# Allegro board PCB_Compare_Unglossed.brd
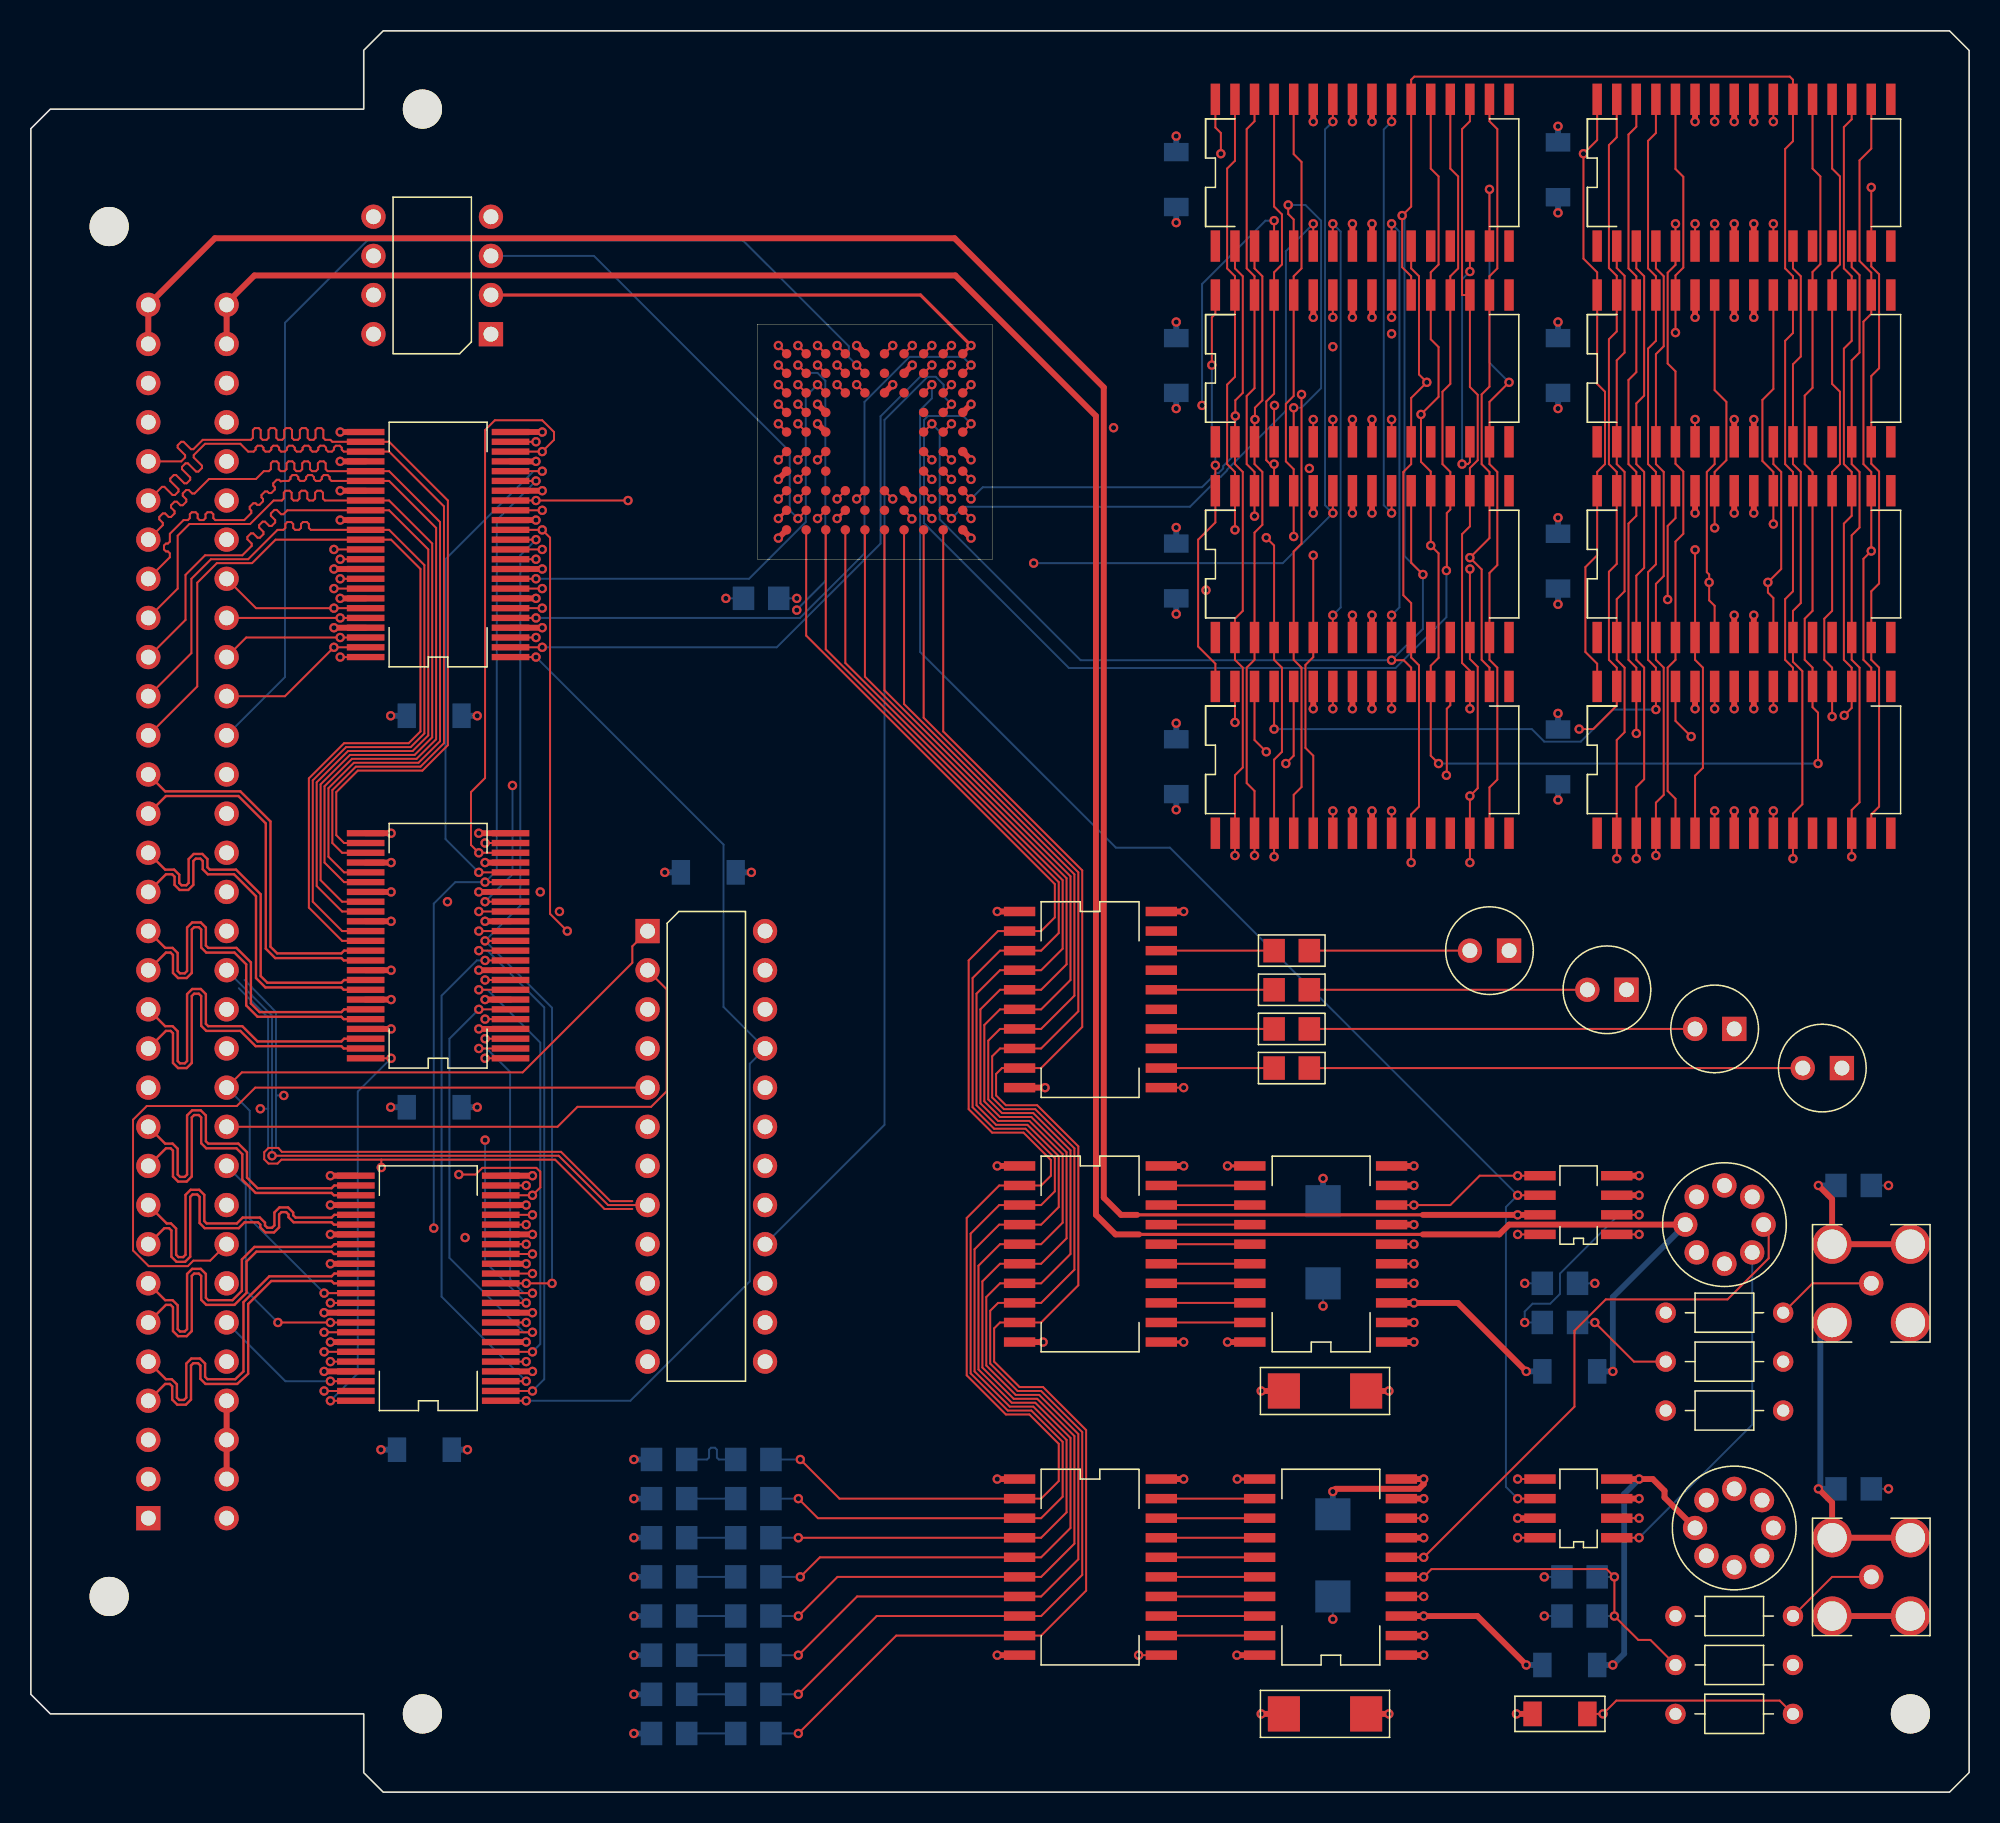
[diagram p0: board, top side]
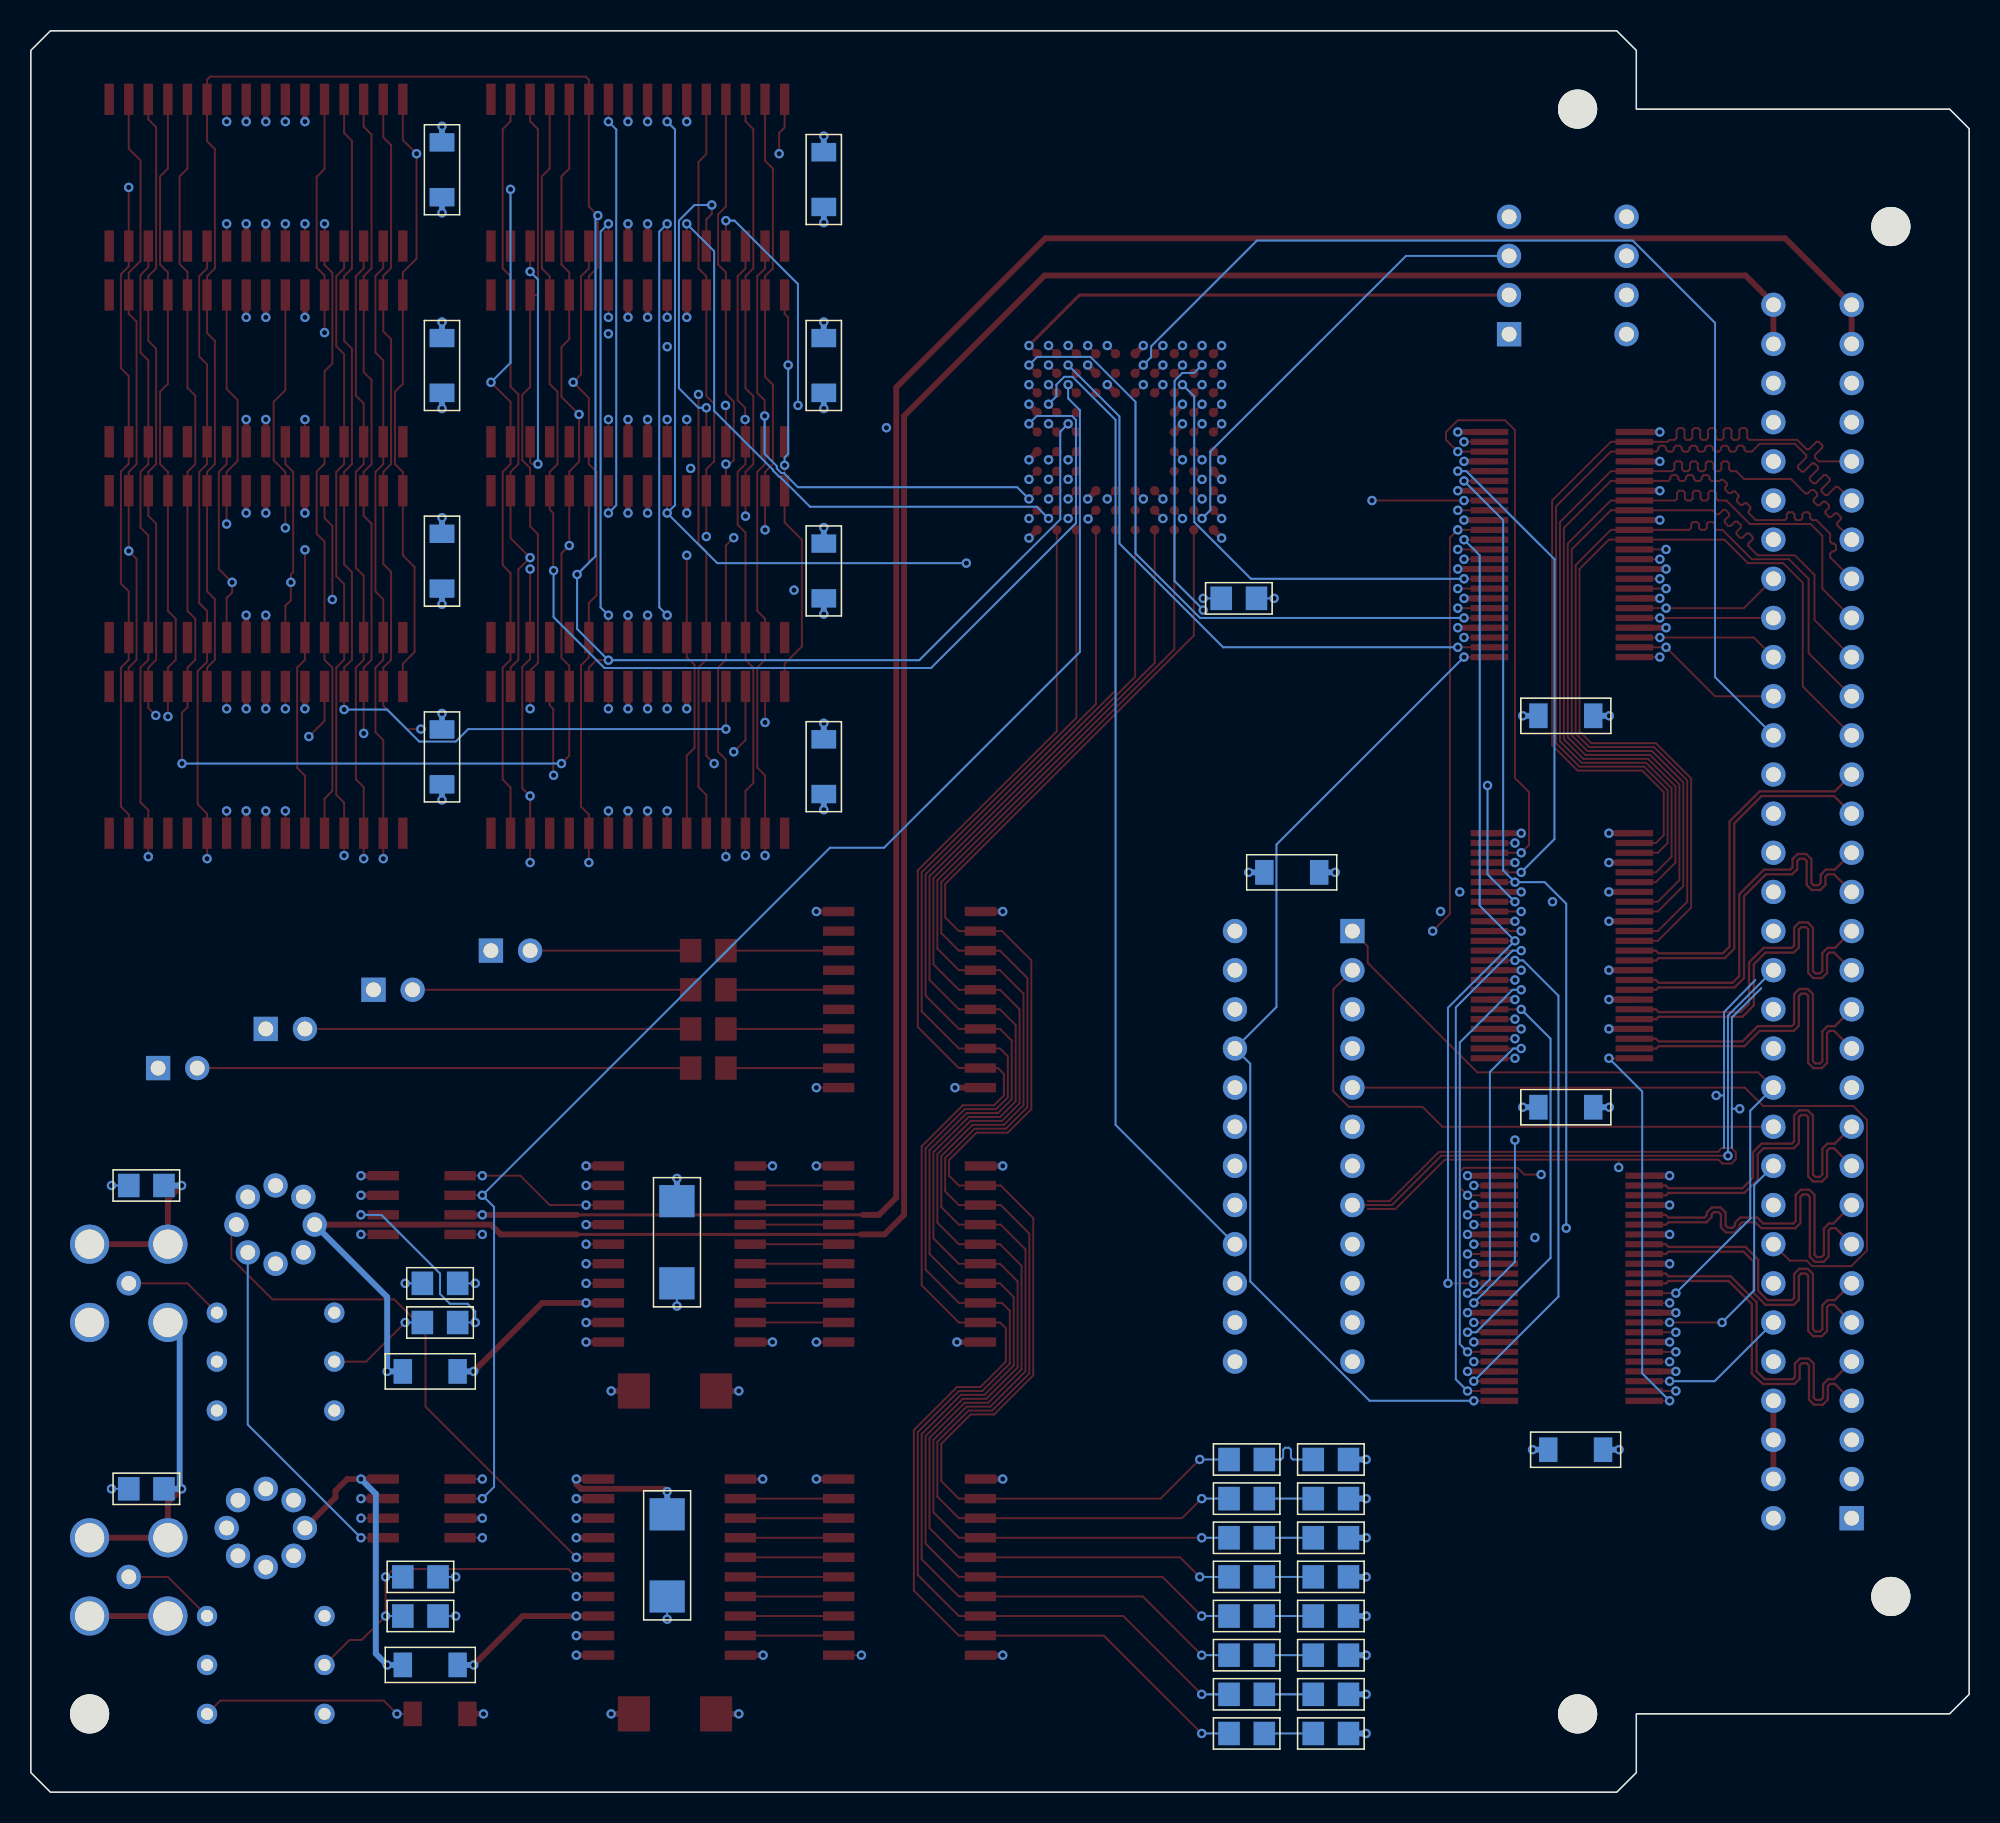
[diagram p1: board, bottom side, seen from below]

Outline 125.73 x 114.3 mm; copper layers: TOP, GND, INNER_1, INNER_2, VCC, BOTTOM. Coordinates in mm from the lower left corner of the outline.

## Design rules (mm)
constraint set DEFAULT: min track width 0.127
net group BNC2: nets BNC2 OUTA
net group BNC3: nets BNC3 OUTB
net group DC_NETS: nets AGND GND_EARTH
net group DP_A8_A9: nets A8 A9
net group DP_A10_A11: nets A10 A11
net group DP_A12_A13: nets A12 A13
net group DP_A14_A15: nets A14 A15
net group DP_D8_D9: nets D8 D9
net group DP_D10_D11: nets D10 D11
net group DP_D12_D13: nets D12 D13
net group DP_D14_D15: nets D14 D15
net group Q0: nets Q0 Q1
net group Q2: nets Q2 Q3
net group Q4: nets Q4 Q5
net group Q6: nets Q6 Q7
net group VCLKC: nets N409523 VCLKC
net group VD0: nets N14855 VD0
net group VD1: nets N14853 VD1
net group VD2: nets N14849 VD2
net group VD3: nets N14843 VD3
net group VD4: nets N15161 VD4
net group VD5: nets N15155 VD5
net group VD6: nets N15151 VD6
net group VD7: nets N15143 VD7
net group CLOCK: nets DCLK MCLK VCLKA
net group N00036: nets N00036 N282866 N282912
net group N00036_12287: nets N00036_12287 N282866_12286 N282912_12285
net group VREF: nets N00038 N00038_12290 VREF
nets with their own width: min track width 0.381; nets GND V12N V+12 VCC

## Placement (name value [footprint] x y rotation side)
C1  0.1uF  [SM_1206]  27.3 22.23 180 bottom
C2  0.1uF  [SM_1206]  27.94 44.45 180 bottom
C3  0.1uF  [SM_1206]  27.94 69.85 180 bottom
C4  0.1uF  [SM_1206]  45.72 59.69 180 bottom
C5  47PF  [SM_0805]  119.38 39.37 180 bottom
C6  47PF  [SM_0805]  119.38 19.69 180 bottom
C7  3300  [SM_0805]  42.55 6.35 180 bottom
C8  3300  [SM_0805]  42.55 11.43 180 bottom
C9  3300  [SM_0805]  42.55 16.51 180 bottom
C10  3300  [SM_0805]  42.55 21.59 180 bottom
C11  3300  [SM_0805]  42.55 3.81 180 bottom
C12  3300  [SM_0805]  42.55 8.89 180 bottom
C13  3300  [SM_0805]  42.55 13.97 180 bottom
C14  3300  [SM_0805]  42.55 19.05 180 bottom
C15  0.1uF  [SM_1206]  99.06 103.5 90 bottom
C16  0.1uF  [SM_1206]  99.06 78.11 90 bottom
C17  0.1uF  [SM_1206]  99.06 90.8 90 bottom
C18  0.1uF  [SM_1206]  74.3 102.87 90 bottom
C19  0.1uF  [SM_1206]  99.06 65.41 90 bottom
C20  0.1uF  [SM_1206]  74.3 90.8 90 bottom
C21  0.1uF  [SM_1206]  74.3 77.47 90 bottom
C22  0.1uF  [SM_1206]  74.3 64.77 90 bottom
C23  .01uF  [SMC_6032]  81.28 26.03 0 top
C24  .01uF  [SMC_6032]  83.82 33.02 90 bottom
C25  0.1uF  [SM_1206]  101.6 27.3 180 bottom
C26  .01uF  [SMC_6032]  81.28 5.08 0 top
C27  .01uF  [SMC_6032]  84.45 12.7 90 bottom
C28  0.1uF  [SM_1206]  101.6 8.25 180 bottom
D1  -  [LED]  95.88 54.61 180 top
D2  -  [LED]  103.5 52.07 180 top
D3  -  [LED]  110.49 49.53 180 top
D4  -  [LED]  117.47 46.99 180 top
J1  CON64  [DIN64]  7.62 17.78 0 top
J2  -  [BNC]  119.38 33.02 0 top
J3  -  [BNC]  119.38 13.97 0 top
L1  50  [IND300]  106.04 31.12 0 top
L2  50  [IND300]  106.68 11.43 0 top
L3  50  [IND300]  113.66 24.77 180 top
L4  50  [IND300]  113.66 27.94 180 top
L5  50  [IND300]  114.3 5.08 180 top
L6  50  [IND300]  114.3 8.25 180 top
NOREF  -  []  -30.48 -55.88 0 top
NOREF#2  -  []  259.08 129.54 0 top
NOREF#3  -  [unnamed#2]  25.4 5.08 0 top
R1  150  [SM_0805]  80.64 54.61 0 top
R2  150  [SM_0805]  80.64 52.07 0 top
R3  150  [SM_0805]  80.64 49.53 0 top
R4  150  [SM_0805]  80.64 46.99 0 top
R5  2K  [SM_0805]  48.51 77.47 180 bottom
R6  10K  [SM_0805]  45.72 6.35 0 bottom
R7  10K  [SM_0805]  45.72 11.43 0 bottom
R8  10K  [SM_0805]  45.72 16.51 0 bottom
R9  10K  [SM_0805]  45.72 21.59 0 bottom
R10  10K  [SM_0805]  45.72 3.81 0 bottom
R11  10K  [SM_0805]  45.72 8.89 0 bottom
R12  10K  [SM_0805]  45.72 13.97 0 bottom
R13  10K  [SM_0805]  45.72 19.05 0 bottom
R14  1/4w  [SM_1206]  100.97 5.08 180 top
R15  100  [SM_0805]  100.33 30.48 180 bottom
R16  100  [SM_0805]  100.33 33.02 180 bottom
R17  100  [SM_0805]  101.6 13.97 180 bottom
R18  100  [SM_0805]  101.6 11.43 180 bottom
U1  FCT16245  [SOIC48]  30.48 25.4 180 top
U2  20L10  [DIP24]  40 55.88 0 top
U3  FCT16245  [SOIC48]  31.11 47.62 180 top
U4  FCT16245  [SOIC48]  31.11 73.66 180 top
U5  EPF8282A_LCC  [BGA_84]  54.74 87.63 0 top
U6  74ACT574  [SOIC20]  64.13 57.15 0 top
U7  EPC1064  [DIP8]  29.84 94.61 180 top
U8  74ACT574  [SOIC20]  64.13 40.64 0 top
U9  74ACT574  [SOIC20]  64.13 20.32 0 top
U10  TC55B4257  [SOIC32]  76.84 62.23 90 top
U11  TC55B4257  [SOIC32]  101.6 100.33 90 top
U12  TC55B4257  [SOIC32]  101.6 62.23 90 top
U13  TC55B4257  [SOIC32]  76.84 87.63 90 top
U14  TC55B4257  [SOIC32]  76.84 74.93 90 top
U15  TC55B4257  [SOIC32]  76.84 100.33 90 top
U16  TC55B4257  [SOIC32]  101.6 74.93 90 top
U17  TC55B4257  [SOIC32]  101.6 87.63 90 top
U18  TLC5602A  [SOIC20]  88.27 29.21 180 top
U19  DG419AK  [SOIC8]  102.87 36.2 180 top
U20  TLE2037A  [TO-99]  110.49 17.14 0 top
U21  TLC5602A  [SOIC20]  88.9 8.89 180 top
U22  TLE2037A  [TO-99]  109.85 36.83 0 top
U23  DG419AK  [SOIC8]  102.87 16.51 180 top

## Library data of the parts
C1-C4 = CAP NP: signal model: DEFAULT_CAPACITOR_100000pF_2_1
C5 = CAP: signal model: DEFAULT_CAPACITOR_47pF_2_1; room: CHAN1
C6 = CAP: signal model: DEFAULT_CAPACITOR_47pF_2_1; room: CHAN2
C7-C14 = CAP: signal model: DEFAULT_RESISTOR_3300OHM_2_1
C15-C22 = CAP NP: signal model: DEFAULT_CAPACITOR_100000pF_2_1; room: MEM
C23 C24 = CAP: signal model: DEFAULT_CAPACITOR_10000pF_2_1; room: CHAN1
C25 = CAP NP: signal model: DEFAULT_CAPACITOR_100000pF_2_1; room: CHAN1
C26 C27 = CAP: signal model: DEFAULT_CAPACITOR_10000pF_2_1; room: CHAN2
C28 = CAP NP: signal model: DEFAULT_CAPACITOR_100000pF_2_1; room: CHAN2
D1-D4 = PHOTODIODE
J1 = CON64
J2 = BNC: alternate symbols: (bnc1); room: CHAN1
J3 = BNC: alternate symbols: (bnc1); room: CHAN2
L1 L3 L4 = INDUCTOR: signal model: DEFAULT_RESISTOR_50OHM_2_1; room: CHAN1
L2 L5 L6 = INDUCTOR: signal model: DEFAULT_RESISTOR_50OHM_2_1; room: CHAN2
R1-R4 = R: signal model: DEFAULT_RESISTOR_150OHM_2_1; room: LED
R5 = R: signal model: DEFAULT_RESISTOR_2000OHM_2_1
R6-R13 = R: signal model: DEFAULT_RESISTOR_10000OHM_2_1
R14 = R: signal model: DEFAULT_RESISTOR_0.25OHM_2_1; room: CHAN2
R15 R16 = R: signal model: DEFAULT_RESISTOR_100OHM_2_1; room: CHAN1
R17 R18 = R: signal model: DEFAULT_RESISTOR_100OHM_2_1; room: CHAN2
U1 U3 U4 = FCT16245
U2 = 20L10: alternate symbols: (T:SOIC24;B:SOIC24_PE)
U5 = EPF8282A/LCC_2
U6 = 74ACT574: room: LED
U7 = EPC1064
U8 = 74ACT574: room: CHAN1
U9 = 74ACT574: room: CHAN2
U10-U17 = TC55B4257: room: MEM
U18 = TLC5602A: room: CHAN1
U19 = DG419AK: room: CHAN1
U20 = TLE2037A: room: CHAN1
U21 = TLC5602A: room: CHAN2
U22 = TLE2037A: room: CHAN2
U23 = DG419AK: room: CHAN2

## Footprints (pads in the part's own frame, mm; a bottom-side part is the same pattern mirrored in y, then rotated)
BGA_84
  round 0.61 smd: A1(-5.715,5.715) A2(-4.445,5.715) A3(-3.175,5.715) A4(-1.905,5.715) A5(-0.635,5.715) A6(0.635,5.715) A7(1.905,5.715) A8(3.175,5.715) A9(4.445,5.715) A10(5.715,5.715) B1(-5.715,4.445) B2(-4.445,4.445) B3(-3.175,4.445) B4(-1.905,4.445) B5(-0.635,4.445) B6(0.635,4.445) B7(1.905,4.445) B8(3.175,4.445) B9(4.445,4.445) B10(5.715,4.445) C1(-5.715,3.175) C2(-4.445,3.175) C3(-3.175,3.175) C4(-1.905,3.175) C5(-0.635,3.175) C6(0.635,3.175) C7(1.905,3.175) C8(3.175,3.175) C9(4.445,3.175) C10(5.715,3.175) D1(-5.715,1.905) D2(-4.445,1.905) D3(-3.175,1.905) D8(3.175,1.905) D9(4.445,1.905) D10(5.715,1.905) E1(-5.715,0.635) E2(-4.445,0.635) E3(-3.175,0.635) E8(3.175,0.635) E9(4.445,0.635) E10(5.715,0.635) F1(-5.715,-0.635) F2(-4.445,-0.635) F3(-3.175,-0.635) F8(3.175,-0.635) F9(4.445,-0.635) F10(5.715,-0.635) G1(-5.715,-1.905) G2(-4.445,-1.905) G3(-3.175,-1.905) G8(3.175,-1.905) G9(4.445,-1.905) G10(5.715,-1.905) H1(-5.715,-3.175) H2(-4.445,-3.175) H3(-3.175,-3.175) H4(-1.905,-3.175) H5(-0.635,-3.175) H6(0.635,-3.175) H7(1.905,-3.175) H8(3.175,-3.175) H9(4.445,-3.175) H10(5.715,-3.175) J1(-5.715,-4.445) J2(-4.445,-4.445) J3(-3.175,-4.445) J4(-1.905,-4.445) J5(-0.635,-4.445) J6(0.635,-4.445) J7(1.905,-4.445) J8(3.175,-4.445) J9(4.445,-4.445) J10(5.715,-4.445) K1(-5.715,-5.715) K2(-4.445,-5.715) K3(-3.175,-5.715) K4(-1.905,-5.715) K5(-0.635,-5.715) K6(0.635,-5.715) K7(1.905,-5.715) K8(3.175,-5.715) K9(4.445,-5.715) K10(5.715,-5.715)
BNC
  round 1.575 hole 0.965: 1(0,0)
  round 2.54 hole 1.905: 2(-2.54,2.54) 3(-2.54,-2.54) 4(2.54,2.54) 5(2.54,-2.54)
DIN64
  round 2.54 hole 2.794 unplated: (-2.54,83.82) (-2.54,-5.08)
  rect 1.575x1.575 hole 0.965: 1(0,0)
  round 1.575 hole 0.965: 2(0,2.54) 3(0,5.08) 4(0,7.62) 5(0,10.16) 6(0,12.7) 7(0,15.24) 8(0,17.78) 9(0,20.32) 10(0,22.86) 11(0,25.4) 12(0,27.94) 13(0,30.48) 14(0,33.02) 15(0,35.56) 16(0,38.1) 17(0,40.64) 18(0,43.18) 19(0,45.72) 20(0,48.26) 21(0,50.8) 22(0,53.34) 23(0,55.88) 24(0,58.42) 25(0,60.96) 26(0,63.5) 27(0,66.04) 28(0,68.58) 29(0,71.12) 30(0,73.66) 31(0,76.2) 32(0,78.74) 33(5.08,0) 34(5.08,2.54) 35(5.08,5.08) 36(5.08,7.62) 37(5.08,10.16) 38(5.08,12.7) 39(5.08,15.24) 40(5.08,17.78) 41(5.08,20.32) 42(5.08,22.86) 43(5.08,25.4) 44(5.08,27.94) 45(5.08,30.48) 46(5.08,33.02) 47(5.08,35.56) 48(5.08,38.1) 49(5.08,40.64) 50(5.08,43.18) 51(5.08,45.72) 52(5.08,48.26) 53(5.08,50.8) 54(5.08,53.34) 55(5.08,55.88) 56(5.08,58.42) 57(5.08,60.96) 58(5.08,63.5) 59(5.08,66.04) 60(5.08,68.58) 61(5.08,71.12) 62(5.08,73.66) 63(5.08,76.2) 64(5.08,78.74)
DIP8
  rect 1.575x1.575 hole 0.965: 1(0,0)
  round 1.575 hole 0.965: 2(0,-2.54) 3(0,-5.08) 4(0,-7.62) 5(7.62,-7.62) 6(7.62,-5.08) 7(7.62,-2.54) 8(7.62,0)
DIP24
  rect 1.575x1.575 hole 0.965: 1(0,0)
  round 1.575 hole 0.965: 2(0,-2.54) 3(0,-5.08) 4(0,-7.62) 5(0,-10.16) 6(0,-12.7) 7(0,-15.24) 8(0,-17.78) 9(0,-20.32) 10(0,-22.86) 11(0,-25.4) 12(0,-27.94) 13(7.62,-27.94) 14(7.62,-25.4) 15(7.62,-22.86) 16(7.62,-20.32) 17(7.62,-17.78) 18(7.62,-15.24) 19(7.62,-12.7) 20(7.62,-10.16) 21(7.62,-7.62) 22(7.62,-5.08) 23(7.62,-2.54) 24(7.62,0)
IND300
  round 1.321 hole 0.787: 1(0,0) 2(7.62,0)
LED
  rect 1.575x1.575 hole 0.965: 1(0,0)
  round 1.575 hole 0.965: 2(2.54,0)
SM_0805
  rect 1.397x1.524 smd: 1(0,0) 2(2.286,0)
SM_1206
  rect 1.194x1.6 smd: 1(0,0) 2(3.556,0)
SMC_6032
  rect 2.083x2.286 smd: 1(0,0) 2(5.334,0)
SOIC8
  rect 2.032x0.61 smd: 1(0,0) 2(0,-1.27) 3(0,-2.54) 4(0,-3.81) 5(4.978,-3.81) 6(4.978,-2.54) 7(4.978,-1.27) 8(4.978,0)
SOIC20
  rect 2.032x0.61 smd: 1(0,0) 2(0,-1.27) 3(0,-2.54) 4(0,-3.81) 5(0,-5.08) 6(0,-6.35) 7(0,-7.62) 8(0,-8.89) 9(0,-10.16) 10(0,-11.43) 11(9.195,-11.43) 12(9.195,-10.16) 13(9.195,-8.89) 14(9.195,-7.62) 15(9.195,-6.35) 16(9.195,-5.08) 17(9.195,-3.81) 18(9.195,-2.54) 19(9.195,-1.27) 20(9.195,0)
SOIC32
  rect 2.032x0.61 smd: 1(0,0) 2(0,-1.27) 3(0,-2.54) 4(0,-3.81) 5(0,-5.08) 6(0,-6.35) 7(0,-7.62) 8(0,-8.89) 9(0,-10.16) 10(0,-11.43) 11(0,-12.7) 12(0,-13.97) 13(0,-15.24) 14(0,-16.51) 15(0,-17.78) 16(0,-19.05) 17(9.525,-19.05) 18(9.525,-17.78) 19(9.525,-16.51) 20(9.525,-15.24) 21(9.525,-13.97) 22(9.525,-12.7) 23(9.525,-11.43) 24(9.525,-10.16) 25(9.525,-8.89) 26(9.525,-7.62) 27(9.525,-6.35) 28(9.525,-5.08) 29(9.525,-3.81) 30(9.525,-2.54) 31(9.525,-1.27) 32(9.525,0)
SOIC48
  rect 2.438x0.406 smd: 1(0,0) 2(0,-0.635) 3(0,-1.27) 4(0,-1.905) 5(0,-2.54) 6(0,-3.175) 7(0,-3.81) 8(0,-4.445) 9(0,-5.08) 10(0,-5.715) 11(0,-6.35) 12(0,-6.985) 13(0,-7.62) 14(0,-8.255) 15(0,-8.89) 16(0,-9.525) 17(0,-10.16) 18(0,-10.795) 19(0,-11.43) 20(0,-12.065) 21(0,-12.7) 22(0,-13.335) 23(0,-13.97) 24(0,-14.605) 25(9.398,-14.605) 26(9.398,-13.97) 27(9.398,-13.335) 28(9.398,-12.7) 29(9.398,-12.065) 30(9.398,-11.43) 31(9.398,-10.795) 32(9.398,-10.16) 33(9.398,-9.525) 34(9.398,-8.89) 35(9.398,-8.255) 36(9.398,-7.62) 37(9.398,-6.985) 38(9.398,-6.35) 39(9.398,-5.715) 40(9.398,-5.08) 41(9.398,-4.445) 42(9.398,-3.81) 43(9.398,-3.175) 44(9.398,-2.54) 45(9.398,-1.905) 46(9.398,-1.27) 47(9.398,-0.635) 48(9.398,0)
TO-99
  round 1.575 hole 0.965: 1(0,-2.54) 2(1.803,-1.803) 3(2.54,0) 4(1.803,1.803) 5(0,2.54) 6(-1.803,1.803) 7(-2.54,0) 8(-1.803,-1.803)
unnamed#2
  round 2.54 hole 2.794 unplated: (0,104.14) (0,0) (96.52,0)

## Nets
AGND: C24.2 C25.2 C27.2 C28.2 J1.34 J1.35 J1.36 U18.3 U18.7 U18.10 U19.3 U21.3 U21.7 U21.10 U23.3
GND: C1.2 C2.2 C3.2 C4.2 C7.2 C8.2 C9.2 C10.2 C11.2 C12.2 C13.2 C14.2 C15.2 C16.2 C17.2 C18.2 C19.2 C20.2 C21.2 C22.2 C23.2 C26.2 J1.1 J1.2 J1.3 J1.33 R14.2 U1.4 U1.10 U1.15 U1.21 U1.24 U1.25(G\) U1.28 U1.34 U1.39 U1.45 U2.11 U2.12 U2.13 U3.4 U3.10 U3.15 U3.21 U3.24 U3.25(G\) U3.28 U3.34 U3.39 U3.45 U4.4 U4.10 U4.15 U4.21 U4.24 U4.25(G\) U4.28 U4.34 U4.39 U4.45 U5.A5 U5.C6 U5.D3 U5.D10 U5.E3 U5.F10 U5.K10 U6.1 U6.10 U7.5 U8.1 U8.10 U9.1 U9.10 U10.9 U10.25 U10.27 U11.9 U11.25 U11.27 U12.9 U12.25 U12.27 U13.9 U13.25 U13.27 U14.9 U14.25 U14.27 U15.9 U15.25 U15.27 U16.9 U16.25 U16.27 U17.9 U17.25 U17.27 U18.1 U18.20 U21.1 U21.20
GND_EARTH: C5.2 C6.2 J2.2 J2.3 J2.4 J2.5(GND5) J3.2 J3.3 J3.4 J3.5(GND5)
V12N: J1.31 J1.32 U19.7 U20.4(V-) U22.4(V-) U23.7
VCC: C1.1 C2.1 C3.1 C4.1 C15.1 C16.1 C17.1 C18.1 C19.1 C20.1 C21.1 C22.1 C23.1 C26.1 D1.1 D2.1 D3.1 D4.1 J1.29 J1.30 J1.62 L4.1 L6.1 U1.7 U1.18 U1.31 U1.42 U2.24(VCC) U3.7 U3.18 U3.31 U3.42 U4.7 U4.18 U4.31 U4.42 U5.B7 U5.G1 U5.H7 U5.K1 U6.20 U7.7 U7.8 U8.20 U9.20 U10.8 U10.24 U11.8 U11.24 U12.8 U12.24 U13.8 U13.24 U14.8 U14.24 U15.8 U15.24 U16.8 U16.24 U17.8 U17.24 U18.2 U18.9(VD2) U21.2 U21.9(VD2)
A0: J1.54 U4.47
A1: J1.55 U4.46
A2: J1.56 U4.44
A3: J1.57 U4.43
A4: J1.58 U4.41
A5: J1.59 U4.40
A6: J1.60 U4.38
A7: J1.61 U4.37
A8: J1.13 U3.47
A9: J1.14 U3.46
A10: J1.15 U3.44
A11: J1.16 U3.43
A12: J1.17 U3.41
A13: J1.18 U3.40
A14: J1.19 U3.38
A15: J1.20 U3.37
A16: J1.37 U1.47
A17: J1.38 U1.46
A18: J1.39 U1.44 U2.6
A19: J1.40 U1.43 U2.5
A20: J1.41 U1.41 U2.4
A21: J1.42 U1.40 U2.3
A22: J1.43 U1.38 U2.2
A23: J1.44 U1.37 U2.1
AEN: J1.47 U2.8
BA0: U1.13 U3.13 U4.13 U5.A6
BA1: U1.14 U3.14 U4.14 U5.A7
BA2: U1.16 U3.16 U4.16 U5.A8
BA3: U1.17 U3.17 U4.17 U5.A9
BA4: U1.19 U3.19 U4.19
BA5: U1.20 U3.20 U4.20
BA6: U1.22 U3.22 U4.22
BA7: U1.23 U3.23 U4.23
BD0: U4.12 U5.C5
BD1: U4.11 U5.C4
BD2: U4.9 U5.C3
BD3: U4.8 U5.C2
BD4: U4.6 U5.C1
BD5: U4.5 U5.B10
BD6: U4.3 U5.B9
BD7: U4.2 U5.B8
BD8: U1.12 U3.2
BD9: U1.11 U3.3
BD10: U1.9 U3.5
BD11: U1.8 U3.6
BD12: U1.6 U3.8
BD13: U1.5 U3.9
BD14: U1.3 U3.11
BD15: U1.2 U3.12
BNC2: C5.1 J2.1 L1.2
BNC3: C6.1 J3.1 L2.2
BRD: U2.16 U5.D9
BRESET: U2.15 U5.B2
BWR: U2.17 U5.H2
D0: J1.28 U3.26 U4.26
D1: J1.27 U3.27 U4.27
D2: J1.26 U3.29 U4.29
D3: J1.25 U3.30 U4.30
D4: J1.24 U3.32 U4.32
D5: J1.23 U3.33 U4.33
D6: J1.22 U3.35 U4.35
D7: J1.21 U3.36 U4.36
D8: J1.4 U1.36
D9: J1.5 U1.35
D10: J1.6 U1.33
D11: J1.7 U1.32
D12: J1.8 U1.30
D13: J1.9 U1.29
D14: J1.10 U1.27
D15: J1.11 U1.26
DATA: U5.B4 U7.1
DCLK: U5.A10 U7.2
DDIR: U1.48 U2.20 U3.48 U4.48
DEN: U1.1 U2.21 U4.1
DHEN: U2.22 U3.1
FPGA: U2.18 U5.C10
GAIN: U5.C8 U19.6 U23.6
HS: U2.19 U5.C9
MCLK: J1.52 U5.J1
MRD: J1.46 U2.9
MWR: J1.45 U2.10
N00036_12287: L6.2 R17.1 R18.1 U21.5 U21.8 U23.5(VL)
N00038_12290: C27.1 L5.2 U21.4
N00044_12288: U22.2 U23.1
N00060_12289: U21.6 U22.3
N282866_12286: R17.2 U23.8
N282912_12285: R18.2 U23.2
NCS: U5.B1 U7.4
OE: U5.J2 U7.3(OE)
OUTA: L1.1 U20.6
OUTB: L2.1 U22.6
Q0: R4.1 U6.12(Q8)
Q1: D4.2(CATHODE) R4.2
Q2: R3.1 U6.14
Q3: D3.2(CATHODE) R3.2
Q4: R2.1 U6.16
Q5: D2.2(CATHODE) R2.2
Q6: R1.1 U6.18
Q7: D1.2(CATHODE) R1.2
RA0: U5.H6 U10.5 U11.5 U12.5 U13.5 U14.5 U15.5 U16.5 U17.5
RA1: U5.H8 U10.4 U11.4 U12.4 U13.4 U14.4 U15.4 U16.4 U17.4
RA2: U5.H9 U10.3 U11.3 U12.3 U13.3 U14.3 U15.3 U16.3 U17.3
RA3: U5.H10 U10.2 U11.2 U12.2 U13.2 U14.2 U15.2 U16.2 U17.2
RA4: U5.G8 U10.32 U11.32 U12.32 U13.32 U14.32 U15.32 U16.32 U17.32
RA5: U5.G9 U10.31 U11.31 U12.31 U13.31 U14.31 U15.31 U16.31 U17.31
RA6: U5.G10 U10.30 U11.30 U12.30 U13.30 U14.30 U15.30 U16.30 U17.30
RA7: U5.F8 U10.29 U11.29 U12.29 U13.29 U14.29 U15.29 U16.29 U17.29
RA8: U5.F9 U10.28 U11.28 U12.28 U13.28 U14.28 U15.28 U16.28 U17.28
RA9: U5.E8 U10.22 U11.22 U12.22 U13.22 U14.22 U15.22 U16.22 U17.22
RA10: U5.E9 U10.21 U11.21 U12.21 U13.21 U14.21 U15.21 U16.21 U17.21
RA11: U5.E10 U10.20 U11.20 U12.20 U13.20 U14.20 U15.20 U16.20 U17.20
RA12: U5.G2 U10.19 U11.19 U12.19 U13.19 U14.19 U15.19 U16.19 U17.19
RA13: U5.F2 U10.18 U11.18 U12.18 U13.18 U14.18 U15.18 U16.18 U17.18
RA14: U5.E2 U10.15 U11.15 U12.15 U13.15 U14.15 U15.15 U16.15 U17.15
RA15: U5.D2 U10.14 U11.14 U12.14 U13.14 U14.14 U15.14 U16.14 U17.14
RCS0: U5.J8 U10.6 U14.6
RCS1: U5.J9 U11.6 U15.6
RCS2: U5.J10 U12.6 U16.6
RCS3: U5.F3 U13.6 U17.6
RD0: U5.F1 U14.26 U15.26 U16.26 U17.26
RD1: U5.E1 U14.23 U15.23 U16.23 U17.23
RD2: U5.D1 U14.10 U15.10 U16.10 U17.10
RD3: U5.H1 U14.7 U15.7 U16.7 U17.7
RD4: U5.A1 U10.26 U11.26 U12.26 U13.26
RD5: U5.A2 U10.23 U11.23 U12.23 U13.23
RD6: U5.A3 U10.10 U11.10 U12.10 U13.10
RD7: U5.A4 U10.7 U11.7 U12.7 U13.7
RDY: J1.50 U2.23
RESET: J1.53 U5.B5
RWE: U5.H5 U10.11(W\E\) U11.11(W\E\) U12.11(W\E\) U13.11(W\E\) U14.11(W\E\) U15.11(W\E\) U16.11(W\E\) U17.11(W\E\)
SEL: U2.14 U5.B3
V+12: C25.1 C28.1 J1.63 J1.64 U19.4 U20.7 U22.7 U23.4
VCLKA: U5.J4 U8.11 U18.11 U21.11
VCLKC: R5.2 U9.11
VD0: R9.2 U5.K2 U6.2 U8.2 U9.2
VD1: R13.2 U5.K3 U6.3 U8.3 U9.3
VD2: R8.2 U5.K4 U6.4 U8.4 U9.4
VD3: R12.2 U5.K5 U6.5 U8.5 U9.5
VD4: R7.2 U5.K6 U6.6 U8.6 U9.6
VD5: R11.2 U5.K7 U6.7 U8.7 U9.7
VD6: R6.2 U5.K8 U6.8 U8.8 U9.8
VD7: R10.2 U5.K9(VD7) U6.9 U8.9 U9.9
VREF: L3.1 L5.1 R14.1
WAIT: J1.51 U5.J3
WSTAT: U5.H4 U6.11
N00036: L4.2 R15.1 R16.1 U18.5 U18.8 U19.5(VL)
N00038: C24.1 L3.2 U18.4
N00044: U19.1 U20.2
N00060: U18.6 U20.3
N14843: C13.1 R12.1
N14849: C9.1 R8.1
N14853: C14.1 R13.1
N14855: C10.1 R9.1
N15143: C11.1 R10.1
N15151: C7.1 R6.1
N15155: C12.1 R11.1
N15161: C8.1 R7.1
N58063: U8.19 U18.12
N58118: U8.18 U18.13
N58173: U8.17 U18.14
N58228: U8.16 U18.15
N58283: U8.15 U18.16
N58338: U8.14 U18.17
N58393: U8.13 U18.18
N58448: U8.12(Q8) U18.19
N58834: U9.19 U21.12
N58889: U9.18 U21.13
N58944: U9.17 U21.14
N58999: U9.16 U21.15
N59054: U9.15 U21.16
N59109: U9.14 U21.17
N59164: U9.13 U21.18
N59219: U9.12(Q8) U21.19
N282866: R16.2 U19.8
N282912: R15.2 U19.2
N409523: R5.1 U5.J7

Pads without a net: J1 12 48 49; U2 7; U5 B6 C7 D8 G3 H3 J5 J6; U6 13 15 17 19; U7 6; U10 1 12 13 16 17; U11 1 12 13 16 17; U12 1 12 13 16 17; U13 1 12 13 16 17; U14 1 12 13 16 17; U15 1 12 13 16 17; U16 1 12 13 16 17; U17 1 12 13 16 17; U20 1 5 8; U22 1 5 8

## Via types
v1: diameter 0.61, hole 0.33, TOP to BOTTOM, 458 vias

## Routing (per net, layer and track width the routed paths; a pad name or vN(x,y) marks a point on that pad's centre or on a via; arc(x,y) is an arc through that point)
AGND: length 183.7
  TOP w0.381: U18.7 v1(89.71,36.83) ; J1.36 J1.35 J1.34 ; v1(84.45,19.51) 84.63,19.69 90.04,19.69 90.35,19.99 v1(90.35,20.32) U21.10 ; U21.3 v1(90.35,11.43) 93.83,11.43 v1(97,8.25) ; U18.3 v1(89.71,31.75) 92.56,31.75 v1(97,27.3) ; U23.3 v1(104.32,19.05) ; U19.3 v1(104.32,38.73) ; U18.10 v1(89.71,40.64) ; U21.7 v1(90.35,16.51)
  INNER_1 w0.381: v1(104.32,19.05) 97.18,26.19 97.18,27.13 v1(97,27.3) ; v1(89.71,40.64) 89.08,40 89.08,37.46 v1(89.71,36.83) 88.57,35.69 88.57,32.89 v1(89.71,31.75) 90.35,31.12 v1(90.35,20.32) 89.71,19.69 89.71,17.14 v1(90.35,16.51) 89.2,15.37 89.2,12.57 v1(90.35,11.43)
  INNER_2 w0.381: v1(83.82,39.83) 84.63,40.64 v1(89.71,40.64) ; v1(89.71,36.83) 100.05,36.83 101.96,38.73 v1(104.32,38.73) ; J1.35 81.1,22.86 v1(84.45,19.51)
  BOTTOM w0.381: C27.2 v1(84.45,19.51) ; C24.2 v1(83.82,39.83) ; C25.2 v1(97,27.3) ; C28.2 v1(97,8.25)
GND: length 211
  TOP w0.127: 22.73,41.05 v1(22.73,40.54) ; 22.73,41.05 34.01,41.05 37.21,37.85 39.01,37.85 ; 22.73,41.05 16.26,41.05 16,40.79 15.42,40.79 15.14,41.07 15.14,41.53 15.42,41.81 16.05,41.81 16.28,41.55 34.39,41.55 37.59,38.35 39.01,38.35
  TOP w0.381: 21.72,82.55 v1(20.07,82.55) ; 83.19,97.16 v1(83.19,95.71) ; U17.27 v1(107.95,95.71) ; 21.72,75.56 v1(19.66,75.56) ; U18.20 v1(77.62,29.21) ; U21.1 v1(90.35,8.89) ; U3.15 v1(29.46,56.52) ; U6.1 v1(62.69,57.15) ; U16.25 v1(110.49,83.01) ; U5.D10 v1(60.99,90.07) ; U4.24 v1(33.17,88.27) ; 21.72,86.36 v1(20.07,86.36) ; U11.27 v1(107.95,108.41) ; U5.D3 v1(51.03,90.07) ; 21.72,53.34 v1(23.37,53.34) ; 31.11,60.32 v1(29.46,60.32) ; U16.9 v1(111.76,76.38) ; U11.9 v1(111.76,101.78) ; U18.1 v1(89.71,29.21) ; U3.4 v1(29.06,49.53) ; U1.39 v1(19.02,31.12) ; 83.19,71.75 v1(83.19,70.31) ; U5.K10 v1(60.99,81.38) ; U1.15 v1(32.13,34.29) ; R14.2 v1(96.37,5.08) ; U15.9 v1(87,101.78) ; 83.19,109.86 v1(83.19,108.41) ; U13.25 v1(85.72,95.71) ; U3.10 v1(29.06,53.34) ; U1.25 v1(19.43,40) ; U5.C6 v1(55.91,91.34) ; 21.72,49.53 v1(23.37,49.53) ; U1.10 v1(32.54,31.12) ; U10.25 v1(85.72,70.31) ; U16.27 v1(107.95,83.01) ; U8.1 v1(62.69,40.64) ; U1.4 v1(32.54,27.3) ; U21.20 v1(78.23,8.89) ; 60.45,87 v1(60.99,86.46) ; U1.24 v1(32.54,40) ; C26.2 v1(88.09,5.08) ; 83.19,84.45 v1(83.19,83.01) ; U11.25 v1(110.49,108.41) ; 21.72,60.32 v1(23.37,60.32) ; U9.1 v1(62.69,20.32) ; U4.21 v1(32.77,86.36) ; U10.9 v1(87,63.68) ; 21.72,79.38 v1(19.66,79.38) ; U8.10 v1(65.66,29.21) ; U1.21 v1(32.13,38.1) ; 21.72,56.52 v1(23.37,56.52) ; U12.25 v1(110.49,70.31) ; U14.9 v1(87,76.38) ; U1.28 v1(19.43,38.1) ; U9.10 v1(62.69,8.89) ; U15.25 v1(85.72,108.41) ; U1.45 v1(19.02,27.3) ; U5.E3 v1(51.03,88.8) ; U4.10 v1(33.17,79.38) ; U4.15 v1(32.77,82.55) ; 21.72,88.27 v1(20.07,88.27) ; C23.2 v1(88.09,26.03) ; U6.10 v1(65.79,45.72) ; U17.25 v1(110.49,95.71) ; U13.9 v1(87,89.08) ; U3.24 v1(29.06,62.23) ; U14.25 v1(85.72,83.01) ; U5.A5 v1(53.57,93.88) ; U4.4 v1(33.17,75.56) ; 21.72,62.23 v1(23.37,62.23) ; U12.9 v1(111.76,63.68) ; U1.34 v1(19.43,34.29) ; U12.27 v1(107.95,70.31) ; U17.9 v1(111.76,89.08)
  BOTTOM w0.127: 15.39,44.35 15.39,50.27 13.49,52.17 ; 15.39,44.35 v1(14.88,44.35) ; 15.39,44.35 15.39,41.81 ; 15.9,45.21 v1(16.41,45.21) ; 15.9,45.21 15.9,41.81 ; 15.9,45.21 15.9,50.62 13.87,52.7
  BOTTOM w0.381: C22.2 v1(74.3,69.37) ; C15.2 v1(99.06,108.1) ; C1.2 v1(22.71,22.23) ; C10.2 v1(39.12,21.59) ; C2.2 v1(23.34,44.45) ; C14.2 v1(39.12,19.05) ; C20.2 v1(74.3,95.4) ; C21.2 v1(74.3,82.07) ; C12.2 v1(39.12,8.89) ; C7.2 v1(39.12,6.35) ; C13.2 v1(39.12,13.97) ; C9.2 v1(39.12,16.51) ; C18.2 v1(74.3,107.47) ; C11.2 v1(39.12,3.81) ; C4.2 v1(41.12,59.69) ; C3.2 v1(23.34,69.85) ; C17.2 v1(99.06,95.4) ; C19.2 v1(99.06,70) ; C16.2 v1(99.06,82.7) ; C8.2 v1(39.12,11.43)
GND_EARTH: length 51.7
  TOP w0.381: v1(115.95,39.37) 116.84,38.48 J2.2 J2.4 ; J3.5 J3.3 ; J3.4 J3.2 116.84,18.8 v1(115.95,19.69)
  INNER_1 w0.381: J2.5 J2.4 ; J2.3 J2.2 ; J3.2 J3.3
  BOTTOM w0.381: J2.3 116.08,29.72 116.08,19.81 v1(115.95,19.69) C6.2 ; C5.2 v1(115.95,39.37)
V12N: length 211
  TOP w0.203: 71.75,37.46 90.3,37.46
  TOP w0.381: 71.75,37.46 70.71,37.46 69.6,38.58 69.6,91.16 59.92,100.84 11.94,100.84 J1.32 J1.31 ; U23.7 v1(96.44,17.78) ; 90.3,37.46 v1(96.44,37.46) U19.7
  INNER_1 w0.381: v1(96.44,17.78) 95.3,18.92 95.3,36.32 v1(96.44,37.46)
  INNER_2 w0.381: v1(96.44,37.46) 100.13,41.15 110.52,41.15 111.66,40 U22.4 ; U20.4 112.29,20.4 111.89,20.8 107.67,20.8 105.28,18.41 97.08,18.41 v1(96.44,17.78)
VCC: length 72.5
  TOP w0.381: U1.31 v1(19.43,36.2) ; U13.8 v1(85.72,89.08) ; U1.7 v1(32.13,29.21) ; U5.K1 v1(48.49,81.38) ; U14.8 v1(85.72,76.38) ; U5.G1 v1(48.49,85.19) ; U10.8 v1(85.72,63.68) ; U12.8 v1(110.49,63.68) ; U18.2 v1(89.71,30.48) ; U3.18 v1(29.06,58.42) ; U8.20 v1(74.78,40.64) ; 21.72,51.43 v1(23.37,51.43) ; U4.18 v1(33.17,84.45) ; U9.20 v1(74.78,20.32) ; U18.9 v1(89.71,39.37) ; U11.24 v1(111.76,108.41) ; U3.7 v1(29.46,51.43) ; U1.18 v1(32.54,36.2) ; U21.2 v1(90.35,10.16) ; U16.24 v1(111.76,83.01) ; U21.9 v1(90.35,19.05) ; C26.1 v1(79.81,5.08) ; U6.20 v1(74.78,57.15) ; 21.72,84.45 v1(20.07,84.45) ; U1.42 v1(19.43,29.21) ; U13.24 v1(87,95.71) ; U11.8 v1(110.49,101.78) ; U14.24 v1(87,83.01) ; U5.H7 v1(57.18,83.92) ; U12.24 v1(111.76,70.31) ; 21.72,77.47 v1(20.07,77.47) ; U17.24 v1(111.76,95.71) ; U17.8 v1(110.49,89.08) ; U15.8 v1(85.72,101.78) ; U5.B7 v1(57.18,92.61) ; U4.7 v1(32.77,77.47) ; U16.8 v1(110.49,76.38) ; 21.72,58.42 v1(23.37,58.42) ; U15.24 v1(87,108.41) ; C23.1 v1(79.81,26.03) ; U10.24 v1(87,70.31)
  BOTTOM w0.381: C18.1 v1(74.3,101.85) ; C19.1 v1(99.06,64.39) ; C20.1 v1(74.3,89.79) ; C17.1 v1(99.06,89.79) ; C15.1 v1(99.06,102.49) ; C4.1 v1(46.74,59.69) ; C2.1 v1(28.96,44.45) ; C1.1 v1(28.32,22.23) ; C22.1 v1(74.3,63.75) ; C16.1 v1(99.06,77.09) ; C3.1 v1(28.96,69.85) ; C21.1 v1(74.3,76.45)
A0: length 10.3
  TOP w0.127: U4.47 v1(19.66,74.3) 16.48,71.12 J1.54
A1: length 9.5
  TOP w0.127: J1.55 13.97,74.93 v1(20.07,74.93) U4.46
A2: length 9
  TOP w0.127: 21.72,76.2 v1(20.07,76.2) J1.56
A3: length 9.8
  TOP w0.127: J1.57 14.6,76.83 v1(19.66,76.83) 21.72,76.83
A4: length 10.3
  TOP w0.127: 21.72,78.11 v1(19.66,78.11)
  INNER_2 w0.127: v1(19.66,78.11) 16.48,81.28 J1.58
A5: length 13.1
  TOP w0.127: 21.72,78.74 v1(20.07,78.74)
  INNER_2 w0.127: J1.59 17.27,83.82 20.83,80.26 20.83,79.5 v1(20.07,78.74)
A6: length 16.5
  TOP w0.127: 21.72,80.01 v1(20.07,80.01)
  INNER_1 w0.127: J1.60 11.46,85.12 11.46,81.03 12.47,80.01 v1(20.07,80.01)
A7: length 13.2
  TOP w0.127: 21.72,80.64 v1(19.66,80.64)
  INNER_1 w0.127: J1.61 16.48,85.12 16.48,83.82 v1(19.66,80.64)
A8: length 23.8
  TOP w0.152: J1.13 8.76,49.4 9.07,49.4 9.22,49.25 9.22,47.32 9.55,46.99 10.11,46.99 10.44,47.32 10.44,51.66 10.59,51.82 10.9,51.82 11.05,51.66 11.05,49.73 11.38,49.4 13.59,49.4 14.58,48.41 20.14,48.41 20.29,48.26 U3.47
A9: length 23.8
  TOP w0.152: U3.46 20.32,48.89 20.14,48.72 14.71,48.72 13.72,49.71 11.51,49.71 11.35,49.86 11.35,51.79 11.02,52.12 10.46,52.12 10.13,51.79 10.13,47.45 9.98,47.29 9.68,47.29 9.52,47.45 9.52,49.38 9.19,49.71 8.71,49.71 J1.14
A10: length 23.7
  TOP w0.152: J1.15 8.76,54.48 9.07,54.48 9.22,54.33 9.22,53.16 9.55,52.83 10.11,52.83 10.44,53.16 10.44,55.98 10.59,56.13 10.9,56.13 11.05,55.98 11.05,54.81 11.38,54.48 13.21,54.48 13.97,53.72 13.97,51.05 14.71,50.32 20.14,50.32 20.29,50.16 21.72,50.16
A11: length 23.7
  TOP w0.152: J1.16 8.71,54.79 9.19,54.79 9.52,54.46 9.52,53.29 9.68,53.14 9.98,53.14 10.13,53.29 10.13,56.11 10.46,56.44 11.02,56.44 11.35,56.11 11.35,54.94 11.51,54.79 13.33,54.79 14.27,53.85 14.27,51.18 14.83,50.62 20.14,50.62 20.32,50.8 21.72,50.8
A12: length 24
  TOP w0.152: J1.17 8.76,59.56 9.17,59.56 9.32,59.41 9.32,58.88 9.65,58.55 10.21,58.55 10.54,58.88 10.54,60.43 10.69,60.58 11,60.58 11.15,60.43 11.15,59.89 11.48,59.56 13.18,59.56 14.6,58.14 14.6,52.83 15.21,52.22 20.14,52.22 20.29,52.07 21.72,52.07
A13: length 24
  TOP w0.152: J1.18 8.71,59.87 9.3,59.87 9.63,59.54 9.63,59 9.78,58.85 10.08,58.85 10.24,59 10.24,60.55 10.57,60.88 11.13,60.88 11.46,60.55 11.46,60.02 11.61,59.87 13.31,59.87 14.91,58.27 14.91,52.96 15.34,52.53 20.14,52.53 20.32,52.7 21.72,52.7
A14: length 23.8
  TOP w0.152: 21.72,53.98 20.29,53.98 20.14,54.13 15.85,54.13 15.24,54.74 15.24,62.86 13.46,64.64 8.76,64.64 J1.19
A15: length 23.7
  TOP w0.152: J1.20 8.71,64.95 13.59,64.95 15.54,62.99 15.54,54.86 15.98,54.43 20.14,54.43 20.32,54.61 21.72,54.61
A16: length 9.2
  TOP w0.127: U1.47 v1(19.02,26.03)
  INNER_2 w0.127: J1.37 14.73,27.94 16.64,26.03 v1(19.02,26.03)
A17: length 10
  TOP w0.127: U1.46 v1(19.43,26.67)
  BOTTOM w0.127: J1.38 16.51,26.67 v1(19.43,26.67)
A18: length 46.2
  TOP w0.127: U1.44 v1(19.43,27.94)
  INNER_1 w0.127: J1.39 17.78,27.94 v1(19.43,27.94) 24.89,27.94 27.94,24.89 32.41,24.89 35.33,27.81 35.33,38.51 U2.6
A19: length 61.5
  TOP w0.127: J1.40 11.63,34.49 10.54,34.49 10.19,34.14 7.65,34.14 6.63,35.15 6.63,43.64 7.52,44.53 13.36,44.53 14.55,45.72 U2.5 ; U1.43 v1(19.02,28.58)
  INNER_2 w0.127: v1(19.02,28.58) 16.99,30.61 16.99,31.27 J1.40
A20: length 62.2
  TOP w0.127: U1.41 v1(19.02,29.84)
  INNER_1 w0.127: v1(19.02,29.84) 18.29,30.58 18.29,32.51 J1.41
  INNER_2 w0.127: J1.41 13.94,39.34 28.57,39.34 33.4,44.17 47.47,44.17 48.62,45.31 48.62,46.2 47.6,47.22 41.05,47.22 U2.4
A21: length 48.9
  TOP w0.127: U1.40 v1(19.43,30.48) v1(16.03,30.48)
  INNER_2 w0.127: U2.3 37.92,50.8 34.24,47.12 24.59,47.12 23.57,48.13 20.19,48.13 J1.42
  BOTTOM w0.127: v1(16.03,30.48) 13.94,32.56 13.94,39.4 J1.42
A22: length 55.8
  TOP w0.127: J1.43 34.16,43.18 35.46,44.48 40.23,44.48 41.25,45.49 41.25,52.1 U2.2 ; U1.38 v1(19.43,31.75)
  INNER_1 w0.127: J1.43 15.11,43.18 20.19,38.1 20.19,32.51 v1(19.43,31.75)
A23: length 50.2
  TOP w0.127: U2.1 39.01,54.89 39.01,53.82 31.9,46.71 13.69,46.71 J1.44 ; U1.37 v1(19.02,32.38)
  BOTTOM w0.127: v1(19.02,32.38) 14.2,37.21 14.2,44.22 J1.44
AEN: length 38.9
  TOP w0.127: U2.8 37.44,38.1 34.24,41.3 v1(15.65,41.3)
  BOTTOM w0.127: J1.47 15.65,50.39 v1(15.65,41.3)
BA0: length 87.6
  TOP w0.127: U5.A6 v1(55.91,93.88) ; v1(33.81,33.02) v1(32.13,33.02) U1.13 ; U4.13 v1(32.77,81.28) ; U3.13 v1(29.46,55.24)
  INNER_1 w0.127: v1(32.77,81.28) 33.3,81.28 46.41,94.39 55.4,94.39 v1(55.91,93.88)
  BOTTOM w0.127: v1(32.77,81.28) 31.75,80.26 31.75,57.53 v1(29.46,55.24) 33.81,50.9 v1(33.81,33.02)
BA1: length 92.1
  TOP w0.127: U4.14 v1(33.17,81.91) 33.68,81.41 33.68,57 v1(34.8,55.88) ; U5.A7 v1(57.18,93.88) ; U3.14 v1(29.06,55.88) ; U1.14 v1(32.54,33.66)
  INNER_1 w0.127: v1(32.54,33.66) 34.8,35.92 v1(34.8,55.88) ; v1(33.17,81.91) 45.9,94.64 56.41,94.64 v1(57.18,93.88)
  INNER_2 w0.127: v1(34.8,55.88) v1(29.06,55.88)
BA2: length 93.8
  TOP w0.127: U3.16 v1(29.06,57.15) ; U5.A8 v1(58.45,93.88) ; U4.16 v1(33.17,83.19) ; U1.16 v1(32.54,34.92)
  INNER_1 w0.127: v1(32.54,34.92) 33.3,35.69 33.3,56.16 v1(34.29,57.15) 34.29,58.29 32,60.58 32,82.55 32.64,83.19 v1(33.17,83.19) 33.93,83.95 33.93,84.61 44.22,94.89 57.43,94.89 v1(58.45,93.88)
  INNER_2 w0.127: v1(34.29,57.15) v1(29.06,57.15)
BA3: length 93.4
  TOP w0.127: U3.17 v1(29.46,57.78) ; v1(38.73,83.82) v1(32.77,83.82) U4.17 ; U5.A9 v1(59.72,93.88) ; U1.17 v1(32.13,35.56)
  INNER_1 w0.127: v1(59.72,93.88) 59.21,93.37 47.75,93.37 38.73,84.35 v1(38.73,83.82) ; v1(27.03,57.78) 27.03,37.13 v1(28.17,35.99) ; v1(32.77,83.82) 31.24,82.3 v1(31.24,65.33)
  INNER_2 w0.127: v1(32.13,35.56) 28.6,35.56 v1(28.17,35.99) ; v1(27.03,57.78) v1(29.46,57.78)
  BOTTOM w0.127: v1(31.24,65.33) 31.24,59.56 v1(29.46,57.78)
BA4: length 63.4
  TOP w0.127: U3.19 v1(29.46,59.05) ; U4.19 v1(32.77,85.09) ; U1.19 v1(32.13,36.83)
  INNER_2 w0.127: v1(32.13,36.83) 26.37,36.83 v1(26.14,36.6)
  BOTTOM w0.127: v1(26.14,36.6) 26.14,57.66 27.53,59.05 v1(29.46,59.05) 30.23,59.82 30.23,82.55 v1(32.77,85.09)
BA5: length 61.7
  TOP w0.127: U4.20 v1(33.17,85.72) ; U3.20 v1(29.06,59.69) ; U1.20 v1(32.54,37.46)
  INNER_1 w0.127: v1(32.54,37.46) 33.05,37.97 v1(33.05,58.42)
  INNER_2 w0.127: v1(29.06,59.69) 30.61,59.69 31.88,58.42 v1(33.05,58.42)
  BOTTOM w0.127: v1(29.06,59.69) 26.9,61.85 26.9,80.01 32.61,85.72 v1(33.17,85.72)
BA6: length 69.5
  TOP w0.127: U1.22 v1(32.54,38.73) 33.05,39.24 33.05,40.26 32.79,40.51 29.29,40.51 28.85,40.08 v1(27.76,40.08) ; 31.11,87 v1(33.17,87) 33.93,87.76 33.93,88.27 33.17,89.03 30.1,89.03 29.46,88.39 29.46,65.81 28.55,64.9 28.55,61.47 v1(29.06,60.96) U3.22
  INNER_1 w0.127: v1(29.06,60.96) 27.76,59.66 v1(27.76,40.08)
BA7: length 55.7
  TOP w0.127: U1.23 v1(32.13,39.37) ; U4.23 v1(32.77,87.63) ; U3.23 v1(29.46,61.59)
  INNER_1 w0.127: v1(32.13,39.37) 30.84,40.67 30.84,60.22 v1(29.46,61.59) 30.48,62.61 30.48,85.34 v1(32.77,87.63)
BD0: length 28.1
  TOP w0.127: U5.C5 v1(53.57,91.34) ; U4.12 v1(33.17,80.64)
  INNER_2 w0.127: v1(53.57,91.34) 53.57,90.58 51.28,88.29 40.82,88.29 v1(33.17,80.64)
BD1: length 28.9
  TOP w0.127: U5.C4 v1(52.3,91.34) ; U4.11 v1(32.77,80.01)
  INNER_1 w0.127: v1(52.3,91.34) 51.79,91.85 51.79,92.61 51.28,93.12 48.18,93.12 43.61,88.54 43.61,87.88 35.74,80.01 v1(32.77,80.01)
BD2: length 30.7
  TOP w0.127: U4.9 v1(32.77,78.74) ; U5.C3 v1(51.03,91.34)
  BOTTOM w0.127: v1(51.03,91.34) 50.27,90.58 50.27,82.42 46.58,78.74 v1(32.77,78.74)
BD3: length 32.8
  TOP w0.127: U4.8 v1(33.17,78.11) ; U5.C2 v1(49.76,91.34)
  INNER_2 w0.127: v1(33.17,78.11) 32.66,78.11 32.26,78.51 32.26,88.16 33.66,89.56 48.74,89.56 49,89.81 49,90.58 v1(49.76,91.34)
BD4: length 32.8
  TOP w0.127: U5.C1 v1(48.49,91.34) ; U4.6 v1(33.17,76.83)
  INNER_2 w0.127: v1(33.17,76.83) 32.64,76.83 32,77.47 32,88.29 34.54,90.83 47.98,90.83 v1(48.49,91.34)
BD5: length 43.6
  TOP w0.127: U4.5 v1(32.77,76.2) ; U5.B10 v1(60.99,92.61)
  BOTTOM w0.127: v1(60.99,92.61) 60.45,93.14 57,93.14 54.08,90.22 54.08,80.39 49.89,76.2 v1(32.77,76.2)
BD6: length 47.3
  TOP w0.127: U4.3 v1(32.77,74.93) ; U5.B9 v1(59.72,92.61)
  INNER_2 w0.127: v1(32.77,74.93) 31.5,76.2 31.5,88.16 35.18,91.85 52.3,91.85 53.06,92.61 53.06,92.81 53.37,93.12 57.38,93.12 57.86,92.63 57.94,92.63 57.94,92.81 58.24,93.12 59.21,93.12 v1(59.72,92.61)
BD7: length 40.5
  TOP w0.127: U4.2 v1(33.17,74.3) ; U5.B8 v1(58.45,92.61)
  BOTTOM w0.127: v1(33.17,74.3) 48.39,74.3 55.12,81.03 55.12,89.28 v1(58.45,92.61)
BD8: length 22.1
  TOP w0.127: U3.2 v1(29.06,48.26) ; U1.12 v1(32.54,32.38)
  BOTTOM w0.127: v1(32.54,32.38) 31.98,32.38 31.09,33.27 31.09,46.74 29.57,48.26 v1(29.06,48.26)
BD9: length 22.7
  TOP w0.127: U3.3 v1(29.46,48.89) ; U1.11 v1(32.13,31.75)
  INNER_1 w0.127: v1(29.46,42.32) 28.45,43.33 28.45,48.39 28.96,48.89 v1(29.46,48.89)
  BOTTOM w0.127: v1(29.46,42.32) 29.46,34.42 v1(32.13,31.75)
BD10: length 24.1
  TOP w0.127: U1.9 v1(32.13,30.48) ; U3.5 v1(29.46,50.16)
  INNER_1 w0.127: v1(29.46,50.16) 30.58,49.05 30.58,32.03 v1(32.13,30.48)
BD11: length 28.4
  TOP w0.127: U1.8 v1(32.54,29.84) ; U3.6 v1(29.06,50.8)
  BOTTOM w0.127: v1(29.06,50.8) 27.15,48.89 27.15,34.67 31.98,29.84 v1(32.54,29.84)
BD12: length 29.8
  TOP w0.127: U1.6 v1(32.54,28.58) ; U3.8 v1(29.06,52.07)
  BOTTOM w0.127: v1(29.06,52.07) 29.62,52.07 33.05,48.64 33.05,29.08 v1(32.54,28.58)
BD13: length 30.5
  TOP w0.127: U3.9 v1(29.46,52.7) ; U1.5 v1(32.13,27.94)
  INNER_1 w0.127: v1(32.13,27.94) 29.31,30.76 29.31,40.82 28.19,41.94 28.19,51.94 28.96,52.7 v1(29.46,52.7)
BD14: length 34.4
  TOP w0.127: U3.11 v1(29.46,53.98) ; U1.3 v1(32.13,26.67)
  BOTTOM w0.127: v1(29.46,53.98) 28.93,53.98 26.64,51.69 26.64,32.16 v1(32.13,26.67)
BD15: length 35.1
  TOP w0.127: U3.12 v1(29.06,54.61) ; U1.2 v1(32.54,26.03)
  BOTTOM w0.127: v1(32.54,26.03) 33.3,26.8 33.3,50.93 29.62,54.61 v1(29.06,54.61)
BNC2: length 14.4
  TOP w0.127: L1.2 115.57,33.02 J2.1
  INNER_1 w0.127: J2.1 119.38,38.25 v1(120.5,39.37)
  BOTTOM w0.127: C5.1 v1(120.5,39.37)
BNC3: length 13.4
  TOP w0.127: L2.2 116.84,13.97 J3.1
  INNER_1 w0.127: v1(120.5,19.69) 119.38,18.57 J3.1
  BOTTOM w0.127: C6.1 v1(120.5,19.69)
BRD: length 64.1
  TOP w0.127: U5.D9 v1(59.72,90.07)
  BOTTOM w0.127: v1(59.72,90.07) 59.21,90.58 59.21,91.34 58.7,91.85 58.17,91.85 55.37,89.05 55.37,43.31 U2.16
BRESET: length 63.1
  TOP w0.127: U5.B2 v1(49.76,92.61)
  INNER_1 w0.127: U2.15 49.66,35.05 49.66,76.68 v1(49.68,76.71)
  BOTTOM w0.127: v1(49.68,76.71) 49.68,76.73 51.54,78.59 51.54,91.59 51.03,92.1 50.27,92.1 v1(49.76,92.61)
BWR: length 47.5
  TOP w0.127: U5.H2 v1(49.76,83.92)
  INNER_1 w0.127: v1(49.76,83.92) 49.02,83.19 49.02,39.5 U2.17
D0: length 58.6
  TOP w0.127: 21.72,61.59 20.32,61.59 19.81,62.1 19.81,64.9 21.21,66.29 25.4,66.29 27.05,67.95 27.05,83.82 23.24,87.63 19.56,87.63 19.43,87.76 19.1,87.76 18.97,87.88 18.97,88.39 18.85,88.52 18.59,88.52 18.47,88.39 18.47,87.88 18.34,87.76 18.08,87.76 17.96,87.88 17.96,88.39 17.83,88.52 17.58,88.52 17.45,88.39 17.45,87.88 17.32,87.76 17.07,87.76 16.94,87.88 16.94,88.39 16.81,88.52 16.56,88.52 16.43,88.39 16.43,87.88 16.31,87.76 16.05,87.76 15.93,87.88 15.93,88.39 15.8,88.52 15.54,88.52 15.42,88.39 15.42,87.88 15.29,87.76 15.04,87.76 14.91,87.88 14.91,88.39 14.78,88.52 14.53,88.52 14.4,88.39 14.4,87.88 14.27,87.76 11.15,87.76 10.54,87.15 10.39,87.15 9.91,87.63 9.75,87.63 9.52,87.4 9.52,87.25 10.01,86.77 10.01,86.61 9.75,86.36 J1.28
D1: length 60
  TOP w0.127: 21.72,60.96 20.19,60.96 19.56,61.59 19.56,65.02 21.08,66.55 25.27,66.55 26.8,68.07 26.8,83.44 23.24,87 20.29,87 20.17,87.12 20.17,87.25 20.04,87.38 19.79,87.38 19.66,87.25 19.66,87.12 19.53,87 19.28,87 19.15,87.12 19.15,87.25 19.02,87.38 18.77,87.38 18.64,87.25 18.64,87.12 18.52,87 18.26,87 18.14,87.12 18.14,87.25 18.01,87.38 17.75,87.38 17.63,87.25 17.63,87.12 17.5,87 17.25,87 17.12,87.12 17.12,87.25 16.99,87.38 16.74,87.38 16.61,87.25 16.61,87.12 16.48,87 16.23,87 16.1,87.12 16.1,87.25 15.98,87.38 15.72,87.38 15.6,87.25 15.6,87.12 15.47,87 15.21,87 15.09,87.12 15.09,87.25 14.96,87.38 14.71,87.38 14.58,87.25 14.58,87.12 14.45,87 14.1,87 13.59,87.5 11.3,87.5 10.57,86.77 10.57,86.61 11.1,86.08 11.1,85.93 10.87,85.7 10.72,85.7 10.19,86.23 10.03,86.23 9.8,86 9.8,85.85 10.34,85.32 10.34,85.17 10.11,84.94 9.96,84.94 9.42,85.47 9.27,85.47 9.04,85.24 9.04,85.09 9.58,84.56 9.58,84.4 9.35,84.18 9.19,84.18 8.66,84.71 8.51,84.71 J1.27
D2: length 58.5
  TOP w0.127: 21.72,59.69 20.32,59.69 19.3,60.71 19.3,65.15 20.95,66.8 25.15,66.8 26.54,68.2 26.54,82.42 23.24,85.72 19.25,85.72 19.13,85.85 19.13,86.23 19,86.36 18.75,86.36 18.62,86.23 18.62,85.85 18.49,85.72 18.24,85.72 18.11,85.85 18.11,86.23 17.98,86.36 17.73,86.36 17.6,86.23 17.6,85.85 17.48,85.72 17.22,85.72 17.09,85.85 17.09,86.23 16.97,86.36 16.71,86.36 16.59,86.23 16.59,85.85 16.46,85.72 16.21,85.72 16.08,85.85 16.08,86.23 15.95,86.36 15.7,86.36 15.57,86.23 15.57,85.85 15.44,85.72 15.11,85.72 14.6,85.22 11.56,85.22 10.62,84.28 10.46,84.28 10.24,84.51 10.08,84.51 9.86,84.28 9.86,84.12 10.08,83.9 10.08,83.74 9.86,83.52 9.7,83.52 9.47,83.74 9.32,83.74 9.09,83.52 9.09,83.36 9.32,83.13 9.32,82.98 9.09,82.75 8.94,82.75 8.71,82.98 8.56,82.98 8.33,82.75 8.33,82.6 8.56,82.37 8.56,82.22 J1.26
D3: length 58.5
  TOP w0.127: J1.25 9.02,80.14 9.02,80.39 8.89,80.52 8.76,80.52 8.64,80.64 8.64,80.9 8.76,81.03 8.89,81.03 9.02,81.15 9.02,81.66 9.91,82.55 10.19,82.55 10.31,82.68 10.31,82.93 10.44,83.06 10.69,83.06 10.82,82.93 10.82,82.68 10.95,82.55 11.2,82.55 11.33,82.68 11.33,82.93 11.46,83.06 11.71,83.06 11.84,82.93 11.84,82.68 11.96,82.55 13.84,82.55 14.3,83.01 14.3,83.16 14.2,83.26 14.2,83.41 14.43,83.64 14.58,83.64 14.68,83.54 14.83,83.54 15.06,83.77 15.06,83.92 14.96,84.02 14.96,84.18 15.19,84.4 15.34,84.4 15.44,84.3 15.6,84.3 15.82,84.53 15.82,84.68 15.72,84.79 15.72,84.94 15.95,85.17 16.1,85.17 16.21,85.06 16.38,85.09 16.71,85.09 16.84,85.22 16.84,85.34 16.97,85.47 17.22,85.47 17.35,85.34 17.35,85.22 17.48,85.09 17.73,85.09 17.86,85.22 17.86,85.34 17.98,85.47 18.24,85.47 18.36,85.34 18.36,85.22 18.49,85.09 18.75,85.09 18.87,85.22 18.87,85.34 19,85.47 19.25,85.47 19.38,85.34 19.38,85.22 19.51,85.09 23.24,85.09 26.29,82.04 26.29,68.33 25.02,67.06 20.83,67.06 19.05,65.28 19.05,60.32 20.32,59.05 21.72,59.05
D4: length 58.5
  TOP w0.127: 21.72,57.78 20.19,57.78 18.8,59.18 18.8,65.41 20.7,67.31 24.89,67.31 26.04,68.45 26.04,81.03 23.24,83.82 19.08,83.82 18.95,83.95 18.95,84.33 18.82,84.45 18.57,84.45 18.44,84.33 18.44,83.95 18.31,83.82 18.06,83.82 17.93,83.95 17.93,84.33 17.81,84.45 17.55,84.45 17.42,84.33 17.42,83.95 17.3,83.82 17.04,83.82 16.92,83.95 16.92,84.33 16.79,84.45 16.54,84.45 16.41,84.33 16.41,83.95 16.28,83.82 15.75,83.82 14.22,82.3 10.29,82.3 9.52,81.53 9.52,78.11 J1.24
D5: length 58.9
  TOP w0.127: 21.72,57.15 20.19,57.15 18.54,58.8 18.54,65.53 20.57,67.56 24.76,67.56 25.78,68.58 25.78,80.64 23.24,83.19 16.64,83.19 16.38,82.93 16.23,82.93 15.95,83.21 15.8,83.21 15.57,82.98 15.57,82.83 15.85,82.55 15.85,82.4 15.62,82.17 15.47,82.17 15.19,82.45 15.04,82.45 14.81,82.22 14.81,82.07 15.09,81.79 15.09,81.64 14.86,81.41 14.71,81.41 14.43,81.69 14.27,81.69 14.05,81.46 14.05,81.31 14.33,81.03 14.33,80.87 13.72,80.26 11.3,80.26 10.03,78.99 10.03,76.07 J1.23
D6: length 59.1
  TOP w0.127: 21.72,55.88 20.19,55.88 18.29,57.78 18.29,65.66 20.45,67.82 24.64,67.82 25.53,68.71 25.53,79.63 23.24,81.91 18.16,81.91 18.03,82.04 18.03,82.3 17.91,82.42 17.65,82.42 17.53,82.3 17.53,82.04 17.4,81.91 17.14,81.91 17.02,82.04 17.02,82.3 16.89,82.42 16.64,82.42 16.51,82.3 16.51,82.04 16.38,81.91 16,81.91 14.1,80.01 11.68,80.01 10.41,78.74 10.41,73.91 J1.22
D7: length 59.6
  TOP w0.127: J1.21 10.79,71.75 10.79,78.49 12.06,79.76 14.35,79.76 15.87,81.28 23.37,81.28 25.27,79.38 25.27,68.83 24.51,68.07 20.32,68.07 18.03,65.79 18.03,57.4 20.19,55.24 21.72,55.24
D8: length 23.9
  TOP w0.152: U1.36 19.66,33.02 19.51,33.17 15.6,33.17 14.1,31.67 14.1,27.15 13.39,26.49 11.33,26.49 11,26.82 11,27.69 10.85,27.84 10.54,27.84 10.39,27.69 10.39,25.48 10.06,25.15 9.5,25.15 9.17,25.48 9.17,26.34 9.02,26.49 8.71,26.49 J1.4
D9: length 23.9
  TOP w0.152: J1.5 8.76,26.8 9.14,26.8 9.47,26.47 9.47,25.6 9.63,25.45 9.93,25.45 10.08,25.6 10.08,27.81 10.41,28.14 10.97,28.14 11.3,27.81 11.3,26.95 11.46,26.8 13.26,26.8 13.79,27.3 13.79,31.8 15.47,33.48 19.51,33.48 19.68,33.66 U1.35
D10: length 23.9
  TOP w0.152: U1.33 19.66,34.92 19.51,35.08 14.63,35.08 14,34.44 14,32.41 13.21,31.62 11.38,31.62 11.05,31.95 11.05,33.5 10.9,33.66 10.59,33.66 10.44,33.5 10.44,29.92 10.11,29.59 9.55,29.59 9.22,29.92 9.22,31.47 9.07,31.62 8.76,31.62 J1.6
D11: length 23.9
  TOP w0.152: J1.7 8.71,31.93 9.19,31.93 9.52,31.6 9.52,30.05 9.68,29.9 9.98,29.9 10.13,30.05 10.13,33.63 10.46,33.96 11.02,33.96 11.35,33.63 11.35,32.08 11.51,31.93 13.08,31.93 13.69,32.54 13.69,34.57 14.5,35.38 19.51,35.38 19.68,35.56 U1.32
D12: length 23.8
  TOP w0.152: J1.8 8.66,36.6 8.97,36.6 9.12,36.45 9.12,34.75 9.45,34.42 10.01,34.42 10.34,34.75 10.34,38.63 10.49,38.79 10.79,38.79 10.95,38.63 10.95,36.93 11.28,36.6 13.49,36.6 13.87,36.98 14.73,36.98 14.88,36.83 14.88,36.65 15.21,36.32 15.77,36.32 16.1,36.65 16.1,37.49 16.26,37.64 16.56,37.64 16.71,37.49 16.71,37.31 17.04,36.98 19.51,36.98 19.66,36.83 U1.30
D13: length 23.9
  TOP w0.152: J1.9 8.81,36.91 9.09,36.91 9.42,36.58 9.42,34.87 9.58,34.72 9.88,34.72 10.03,34.87 10.03,38.76 10.36,39.09 10.92,39.09 11.25,38.76 11.25,37.06 11.4,36.91 13.36,36.91 13.74,37.29 14.86,37.29 15.19,36.96 15.19,36.78 15.34,36.63 15.65,36.63 15.8,36.78 15.8,37.62 16.13,37.95 16.69,37.95 17.02,37.62 17.02,37.44 17.17,37.29 19.51,37.29 19.68,37.46 U1.29
D14: length 24
  TOP w0.152: J1.10 8.76,41.78 9.07,41.78 9.22,41.63 9.22,39.95 9.55,39.62 10.11,39.62 10.44,39.95 10.44,43.79 10.59,43.94 10.9,43.94 11.05,43.79 11.05,42.11 11.38,41.78 13.33,41.78 13.72,41.4 13.72,39.75 14.58,38.89 19.51,38.89 19.66,38.73 U1.27
D15: length 23.9
  TOP w0.152: J1.11 8.71,42.09 9.19,42.09 9.52,41.76 9.52,40.08 9.68,39.93 9.98,39.93 10.13,40.08 10.13,43.92 10.46,44.25 11.02,44.25 11.35,43.92 11.35,42.24 11.51,42.09 13.46,42.09 14.02,41.53 14.02,39.88 14.71,39.19 19.51,39.19 19.68,39.37 U1.26
DATA: length 24
  TOP w0.127: U5.B4 v1(52.3,92.61)
  INNER_2 w0.127: U7.1 31.09,93.37 51.54,93.37 v1(52.3,92.61)
DCLK: length 33.3
  TOP w0.203: U5.A10 v1(60.99,93.88) 57.71,97.16 U7.2
DDIR: length 81.3
  TOP w0.127: U1.48 v1(19.43,25.4) ; U3.48 v1(23.37,47.62) ; U4.48 v1(20.07,73.66)
  INNER_1 w0.127: v1(23.37,47.62) 20.07,50.93 v1(20.07,73.66)
  INNER_2 w0.127: v1(23.37,47.62) 24.28,46.71 46.63,46.71 U2.20
  BOTTOM w0.127: v1(19.43,25.4) 21.21,27.18 21.21,45.47 v1(23.37,47.62)
DEN: length 68.1
  TOP w0.127: U1.1 v1(32.13,25.4) ; U4.1 v1(32.77,73.66)
  BOTTOM w0.127: v1(32.77,73.66) 44.93,61.49 44.93,50.95 U2.21 46.63,47.27 46.63,33.15 38.89,25.4 v1(32.13,25.4)
DHEN: length 21.9
  TOP w0.127: U3.1 v1(29.46,47.62)
  INNER_2 w0.127: U2.22 46.63,51.79 33.63,51.79 v1(29.46,47.62)
FPGA: length 63.7
  TOP w0.127: U5.C10 v1(60.99,91.34)
  INNER_1 w0.127: U2.18 48.62,41.63 48.62,58.88 47.96,59.54 47.96,86.74 48.72,87.5 59.21,87.5 60.22,88.52 60.22,90.58 v1(60.99,91.34)
GAIN: length 95
  TOP w0.127: U23.6 v1(96.44,19.05) ; U19.6 v1(96.44,38.73) ; U5.C8 v1(58.45,91.34)
  BOTTOM w0.127: v1(96.44,19.05) 95.68,19.81 95.68,37.97 v1(96.44,38.73) 73.89,61.29 70.38,61.29 57.68,73.99 57.68,89.69 58.45,90.45 v1(58.45,91.34)
HS: length 59.5
  TOP w0.127: U5.C9 v1(59.72,91.34)
  INNER_1 w0.127: v1(59.72,91.34) 59.16,91.34 55.91,88.09 48.89,88.09 46.23,85.42 46.23,44.58 U2.19
MCLK: length 43.4
  TOP w0.203: U5.J1 v1(48.49,82.65)
  INNER_2 w0.203: J1.52 31.88,66.04 v1(48.49,82.65)
MRD: length 46
  INNER_2 w0.127: U2.9 34.8,40.77 31.6,40.77 27.94,37.11 12.27,37.11 11.46,37.92 11.46,49.56 J1.46
MWR: length 56.4
  INNER_1 w0.127: U2.10 37.08,30.1 37.08,29.11 32.38,24.41 12.22,24.41 11.71,24.92 11.71,47.27 J1.45
N00036_12287: length 38.8
  TOP w0.127: L6.2 105.05,9.88 104.27,9.88 v1(102.72,11.43) v1(102.72,13.97) 102.21,14.48 90.86,14.48 v1(90.35,13.97) U21.5 ; U23.5 v1(96.44,20.32) ; U21.8 v1(90.35,17.78)
  INNER_1 w0.127: v1(90.35,17.78) 91.11,17.02 91.11,14.73 v1(90.35,13.97)
  INNER_2 w0.127: v1(90.35,17.78) 91.49,17.78 94.03,20.32 v1(96.44,20.32)
  BOTTOM w0.127: R18.1 v1(102.72,11.43) ; R17.1 v1(102.72,13.97)
N00038_12290: length 28.9
  TOP w0.127: U21.4 v1(90.35,12.7)
  INNER_2 w0.127: v1(84.45,11.23) 85.93,12.7 v1(90.35,12.7) 99.06,12.7 L5.2
  BOTTOM w0.127: C27.1 v1(84.45,11.23)
N00044_12288: length 23
  TOP w0.127: U23.1 v1(104.32,16.51)
  BOTTOM w0.127: v1(104.32,16.51) 111.66,23.85 U22.2
N00060_12289: length 37.1
  TOP w0.127: U21.6 v1(90.35,15.24) 100.13,25.02 100.13,29.95 102.16,31.98 110.06,31.98 112.73,34.65 112.73,36.5 U22.3
N282866_12286: length 5.8
  TOP w0.127: U23.8 v1(96.44,16.51)
  INNER_1 w0.127: v1(96.44,16.51) 96.44,15.7 v1(98.17,13.97)
  BOTTOM w0.127: R17.2 v1(98.17,13.97)
N282912_12285: length 11.5
  TOP w0.127: U23.2 v1(104.32,17.78)
  INNER_1 w0.127: v1(98.17,11.43) 100.46,13.72 100.46,13.92 v1(104.32,17.78)
  BOTTOM w0.127: R18.2 v1(98.17,11.43)
NCS: length 30
  TOP w0.127: U5.B1 v1(48.49,92.61)
  INNER_2 w0.127: v1(48.49,92.61) 29.97,92.61 28.57,94.01 28.57,100.97 29.84,102.23
OE: length 30
  TOP w0.127: U5.J2 v1(49.76,82.65)
  BOTTOM w0.127: v1(49.76,82.65) 49.23,83.19 49.23,87 36.53,99.69 29.84,99.69
OUTA: length 13.3
  INNER_1 w0.127: L1.1 108.69,28.47 U20.6
OUTB: length 29.7
  INNER_1 w0.127: U22.6 106.96,38.63 105.18,36.86 105.18,12.93 L2.1
Q0: length 7.3
  TOP w0.127: U6.12 R4.1
Q1: length 32
  TOP w0.127: R4.2 D4.2
Q2: length 7.3
  TOP w0.127: U6.14 R3.1
Q3: length 25
  TOP w0.127: R3.2 D3.2
Q4: length 7.3
  TOP w0.127: U6.16 R2.1
Q5: length 18
  TOP w0.127: R2.2 D2.2
Q6: length 7.3
  TOP w0.127: U6.18 R1.1
Q7: length 10.4
  TOP w0.127: R1.2 D1.2
RA0: length 149.4
  TOP w0.127: U13.5 v1(81.91,89.84) ; v1(82.42,90.7) 82.42,81.03 81.91,80.52 U14.5 81.91,73.48 82.42,72.97 82.42,65.23 81.91,64.72 U10.5 ; v1(81.56,103) 81.56,102.41 81.91,102.06 U15.5 ; U5.H6 v1(55.91,83.92) ; U12.5 106.68,64.47 106.17,64.97 106.17,72.97 106.68,73.48 U16.5 106.68,81.15 107.19,81.66 107.19,85.7 106.68,86.21 U17.5 106.68,92.2 106.17,92.71 106.17,98.6 106.68,99.11 U11.5 v1(106.68,101.78)
  INNER_1 w0.127: v1(82.42,90.7) 82.22,90.7 81.91,90.4 v1(81.91,89.84)
  INNER_2 w0.127: v1(55.91,83.92) 55.91,87.02 59.59,90.7 v1(82.42,90.7) ; v1(106.68,101.78) 105.46,103 v1(81.56,103)
  BOTTOM w0.127: v1(81.56,103) 82.68,103 83.69,101.98 83.69,91.11 82.42,89.84 v1(81.91,89.84)
RA1: length 140.9
  TOP w0.127: 80.64,87.63 80.64,89.97 v1(80.67,89.99) ; v1(80.14,81.41) 80.64,80.9 80.64,73.48 81.15,72.97 81.15,67.51 80.64,67.01 v1(80.64,60.71) ; U11.4 105.41,98.88 105.92,98.37 105.92,93.83 105.41,93.32 U17.4 105.41,86.18 105.92,85.67 105.92,78.92 105.41,78.41 U16.4 105.41,73.48 105.92,72.97 105.92,64.72 105.41,64.21 U12.4 v1(105.41,60.78) ; v1(80.64,101.98) 80.64,100.33 ; U5.H8 v1(58.45,83.92)
  INNER_1 w0.127: v1(58.45,83.92) 58.98,84.45 58.98,86.46 59.49,86.97 72.95,86.97 v1(75.97,89.99) ; v1(80.14,81.41) 80.14,89.46 v1(80.67,89.99) ; v1(80.64,60.71) 81.03,61.09 105.11,61.09 v1(105.41,60.78)
  INNER_2 w0.127: v1(75.97,89.99) v1(80.67,89.99)
  BOTTOM w0.127: v1(75.97,89.99) 75.97,97.87 80.09,101.98 v1(80.64,101.98)
RA2: length 130.3
  TOP w0.127: U5.H9 v1(59.72,83.92) ; U15.3 79.38,98.88 79.88,98.37 79.88,90.32 79.4,89.84 v1(79.4,89.08) 79.38,89.05 U13.3 79.38,86.18 79.88,85.67 79.88,82.25 79.38,81.74 U14.3 79.38,73.48 78.87,72.97 78.87,65.48 79.38,64.97 U10.3 v1(79.38,60.78) ; v1(104.14,60.58) U12.3 104.14,65.23 104.65,65.74 104.65,72.97 104.14,73.48 U16.3 104.14,78.94 104.65,79.45 104.65,85.67 104.14,86.18 U17.3 104.14,90.12 104.65,90.63 104.65,98.37 104.14,98.88 U11.3
  INNER_1 w0.127: v1(79.4,89.08) 79.4,88.11 77.34,86.06 77.34,85.9 77.04,85.6 76.89,85.6 75.97,84.68 60.48,84.68 v1(59.72,83.92)
  INNER_2 w0.127: v1(104.14,60.58) 103.5,61.21 79.81,61.21 v1(79.38,60.78)
RA3: length 128.9
  TOP w0.127: 78.1,100.33 78.1,98.88 78.61,98.37 78.61,90.8 78.13,90.32 v1(78.13,89.31) 78.1,89.28 78.1,86.18 78.61,85.67 78.61,76.66 78.1,76.15 78.1,73.48 78.61,72.97 78.61,66.5 78.1,65.99 v1(78.1,60.78) ; U5.H10 v1(60.99,83.92) ; U11.2 102.87,98.91 103.38,98.4 103.38,93.42 102.87,92.91 U17.2 102.87,86.18 103.38,85.67 103.38,77.93 102.87,77.42 U16.2 102.87,73.48 103.38,72.97 103.38,68.78 102.87,68.28 U12.2 v1(102.87,60.58)
  INNER_1 w0.127: v1(102.87,60.58) 102.62,60.83 81.48,60.83 80.85,60.2 78.69,60.2 v1(78.1,60.78)
  BOTTOM w0.127: v1(60.99,83.92) 61.75,84.68 75.97,84.68 76.89,85.6 77.04,85.6 77.34,85.9 77.34,86.06 78.13,86.84 v1(78.13,89.31)
RA4: length 127.1
  TOP w0.127: U15.32 76.84,108.03 77.19,107.67 v1(77.19,106.32) ; v1(76.61,92.61) 76.61,95.71 76.84,95.94 U13.32 ; U5.G8 v1(58.45,85.19) ; U12.32 101.6,73.23 100.84,73.99 100.84,79.5 101.6,80.26 U16.32 101.6,85.67 102.11,86.18 102.11,90.88 101.6,91.39 U17.32 101.6,98.63 100.71,99.52 v1(100.71,106.32) 101.6,107.21 U11.32 ; v1(76.84,86.11) U14.32 76.84,82.4 75.72,81.28 75.72,74.35 76.84,73.23 U10.32
  INNER_1 w0.127: v1(76.61,92.61) 77.19,93.19 v1(77.19,106.32)
  INNER_2 w0.127: v1(76.84,86.11) 76.33,86.11 75.95,85.72 59.54,85.72 59,85.19 v1(58.45,85.19) ; v1(77.19,106.32) v1(100.71,106.32)
  BOTTOM w0.127: v1(76.84,86.11) 76.84,86.61 76.61,86.84 v1(76.61,92.61)
RA5: length 131.4
  TOP w0.127: v1(100.43,68.99) 101.35,68.99 102.87,70.51 U12.31 102.87,72.97 102.36,73.48 102.36,79.2 102.87,79.71 U16.31 102.87,85.67 102.36,86.18 102.36,94.28 102.87,94.79 U17.31 102.87,98.4 102.36,98.91 102.36,106.88 102.87,107.39 U11.31 ; 78.1,71.75 v1(78.1,69.42) ; v1(78.1,81.91) 78.1,85.67 77.6,86.18 77.6,91.34 78.1,91.85 78.1,98.37 77.6,98.88 77.6,105.36 78.1,105.87 78.1,109.86 ; U5.G9 v1(59.72,85.19)
  INNER_1 w0.127: v1(78.1,69.42) v1(78.1,81.91)
  INNER_2 w0.127: v1(78.1,81.91) 77.06,81.91 75.82,83.16 60.99,83.16 60.48,83.67 60.48,84.43 v1(59.72,85.19) ; v1(78.1,69.42) 78.87,70.18 81.31,70.18 82.5,68.99 v1(100.43,68.99)
RA6: length 135.4
  TOP w0.127: U10.30 79.38,68.28 v1(80.14,67.51) ; v1(104.14,68.71) U12.30 104.14,72.97 103.63,73.48 103.63,82.32 104.14,82.83 U16.30 104.14,85.67 103.63,86.18 103.63,91.64 104.14,92.15 U17.30 104.14,98.37 103.63,98.88 103.63,107.57 104.14,108.08 U11.30 ; v1(79.38,82.8) U14.30 79.38,85.67 78.87,86.18 78.87,90.6 79.38,91.11 U13.30 79.38,98.37 78.87,98.88 78.87,107.92 79.38,108.43 U15.30 ; U5.G10 v1(60.99,85.19)
  INNER_1 w0.127: v1(80.14,67.51) 78.99,68.66 78.99,82.42 v1(79.38,82.8)
  INNER_2 w0.127: v1(104.14,68.71) 101.07,68.71 99.87,67.51 v1(80.14,67.51) ; v1(60.99,85.19) 76.99,85.19 v1(79.38,82.8)
